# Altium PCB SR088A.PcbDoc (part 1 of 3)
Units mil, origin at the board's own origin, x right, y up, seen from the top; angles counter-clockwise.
Board outline 5010 x 3800 mil, 6 copper layers (Top Layer, Signal Layer 1, Signal Layer 2, Signal Layer 3, Signal Layer 4, Bottom Layer), stack 61.4 mil thick; 199 components, 82 nets, 478 pads, 1347 vias.
Unrouted connection lines stored in the file: 13.
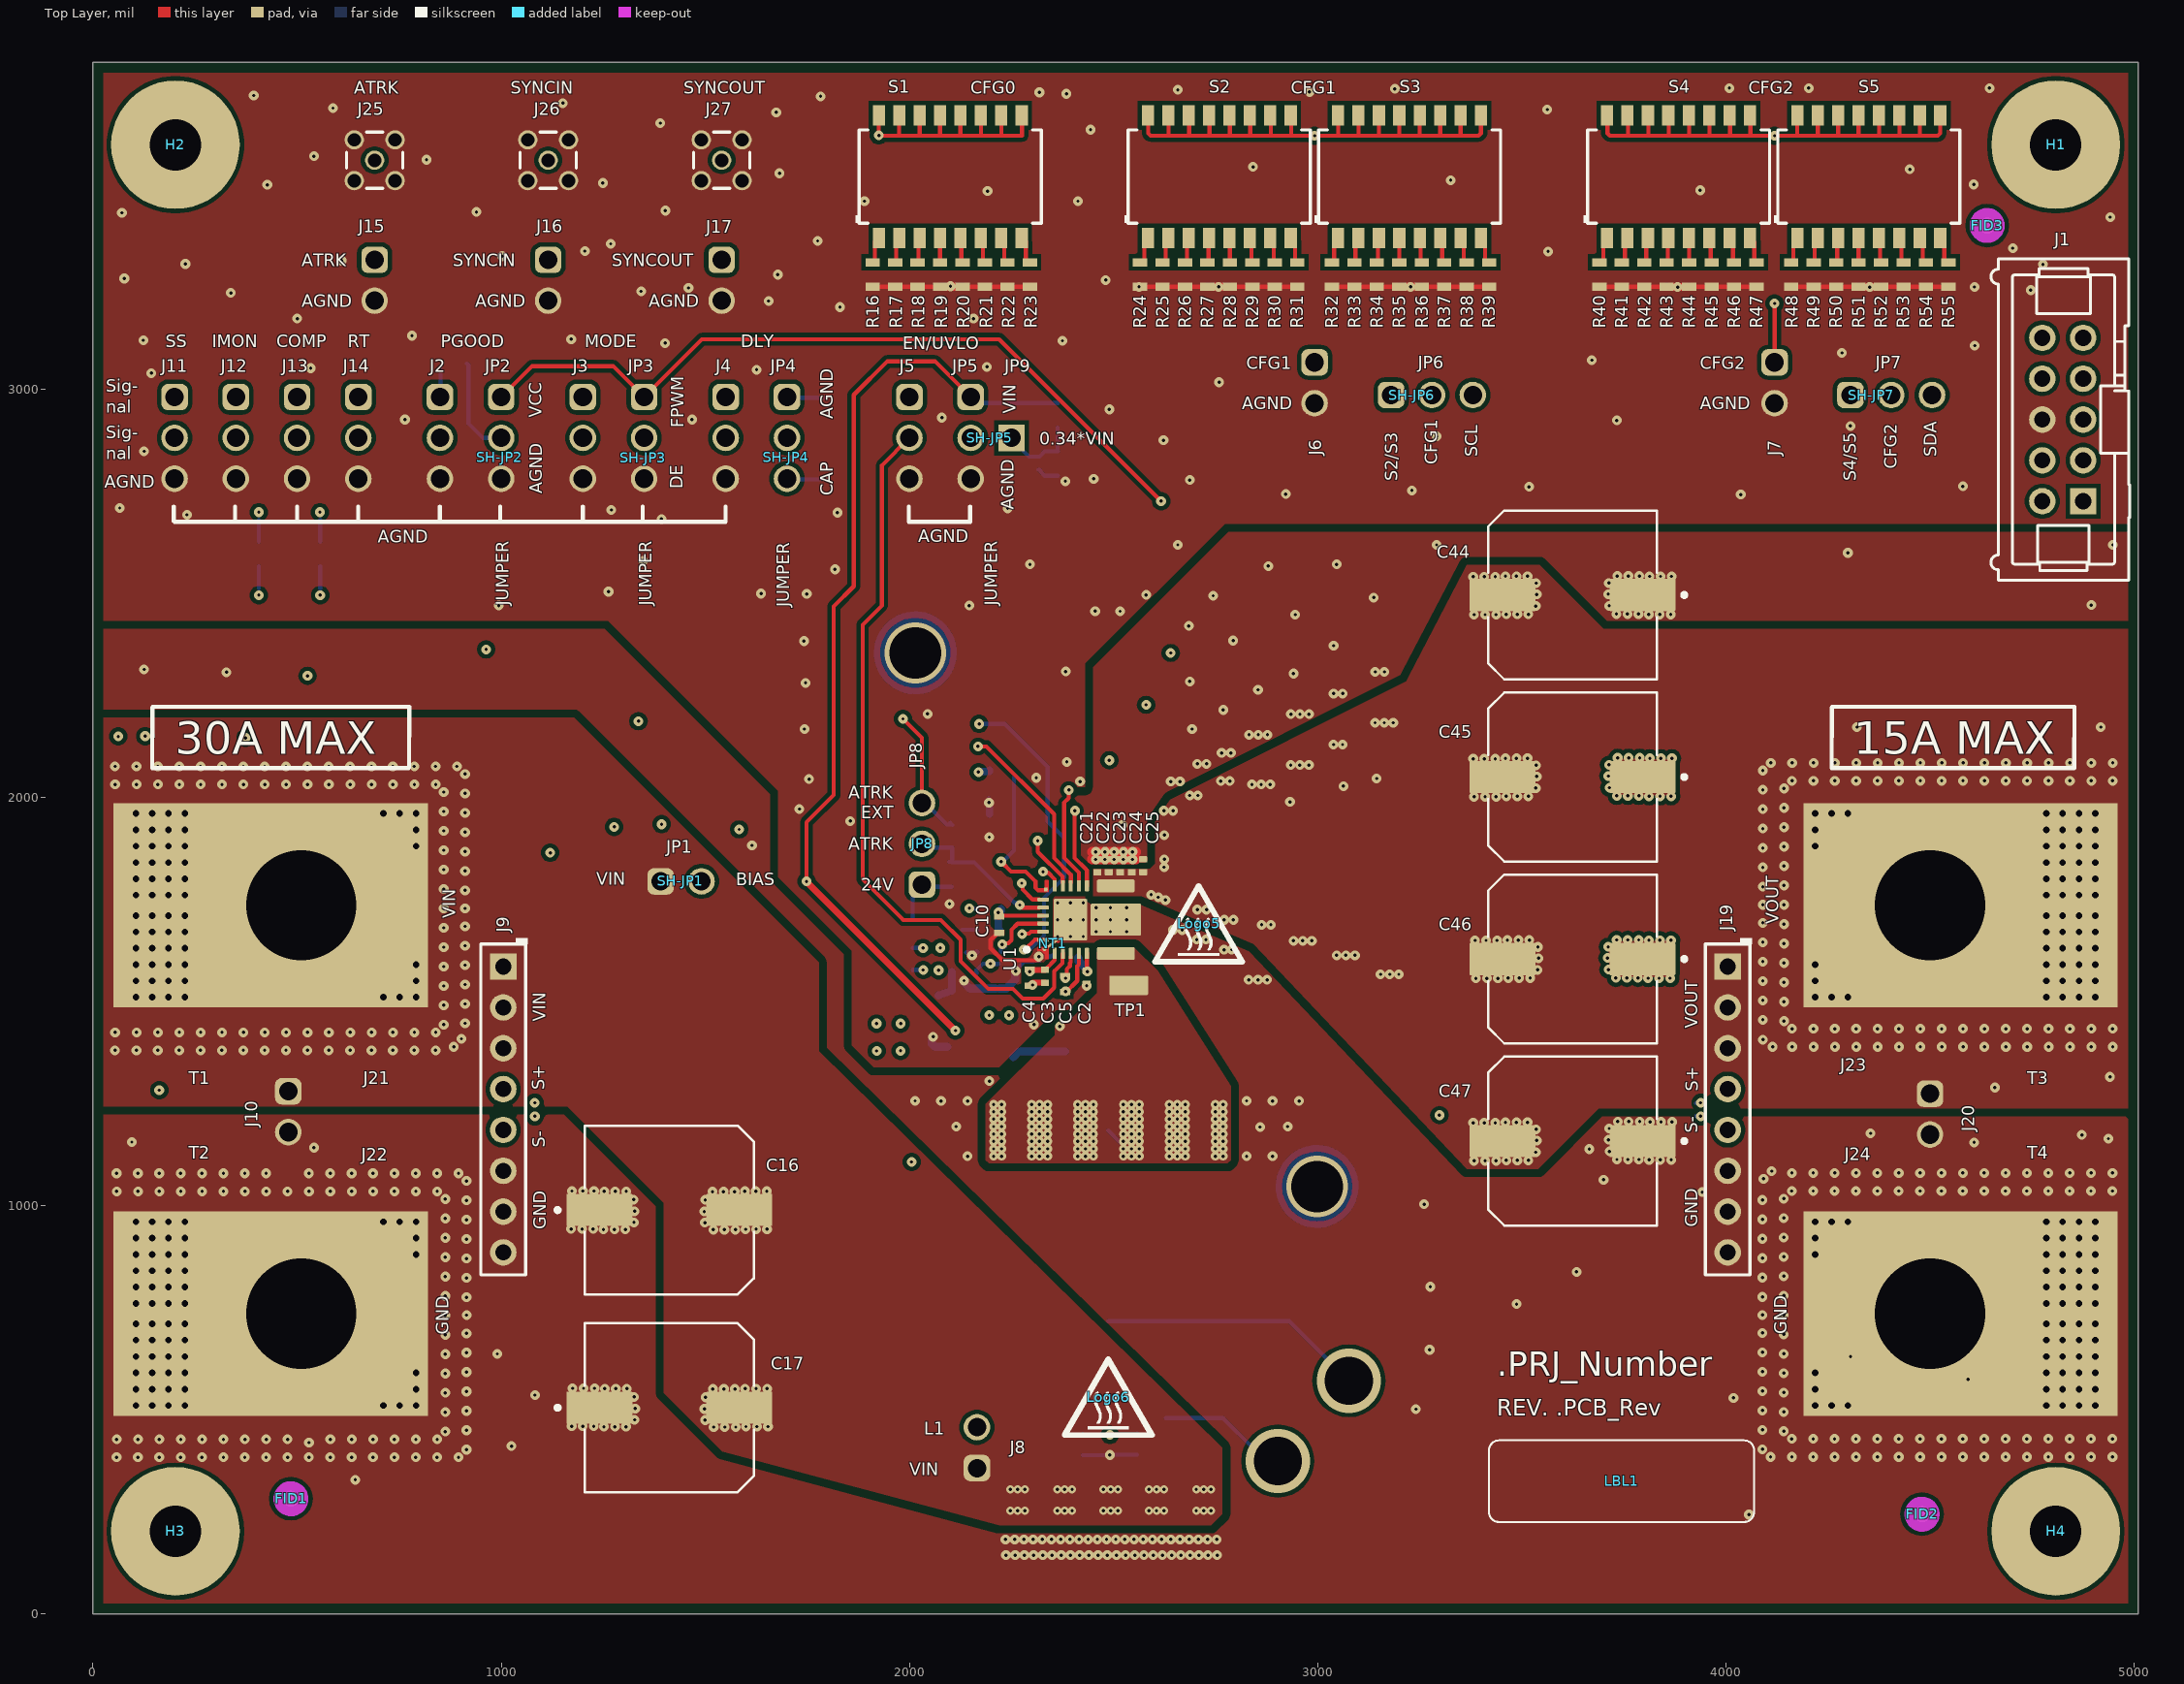
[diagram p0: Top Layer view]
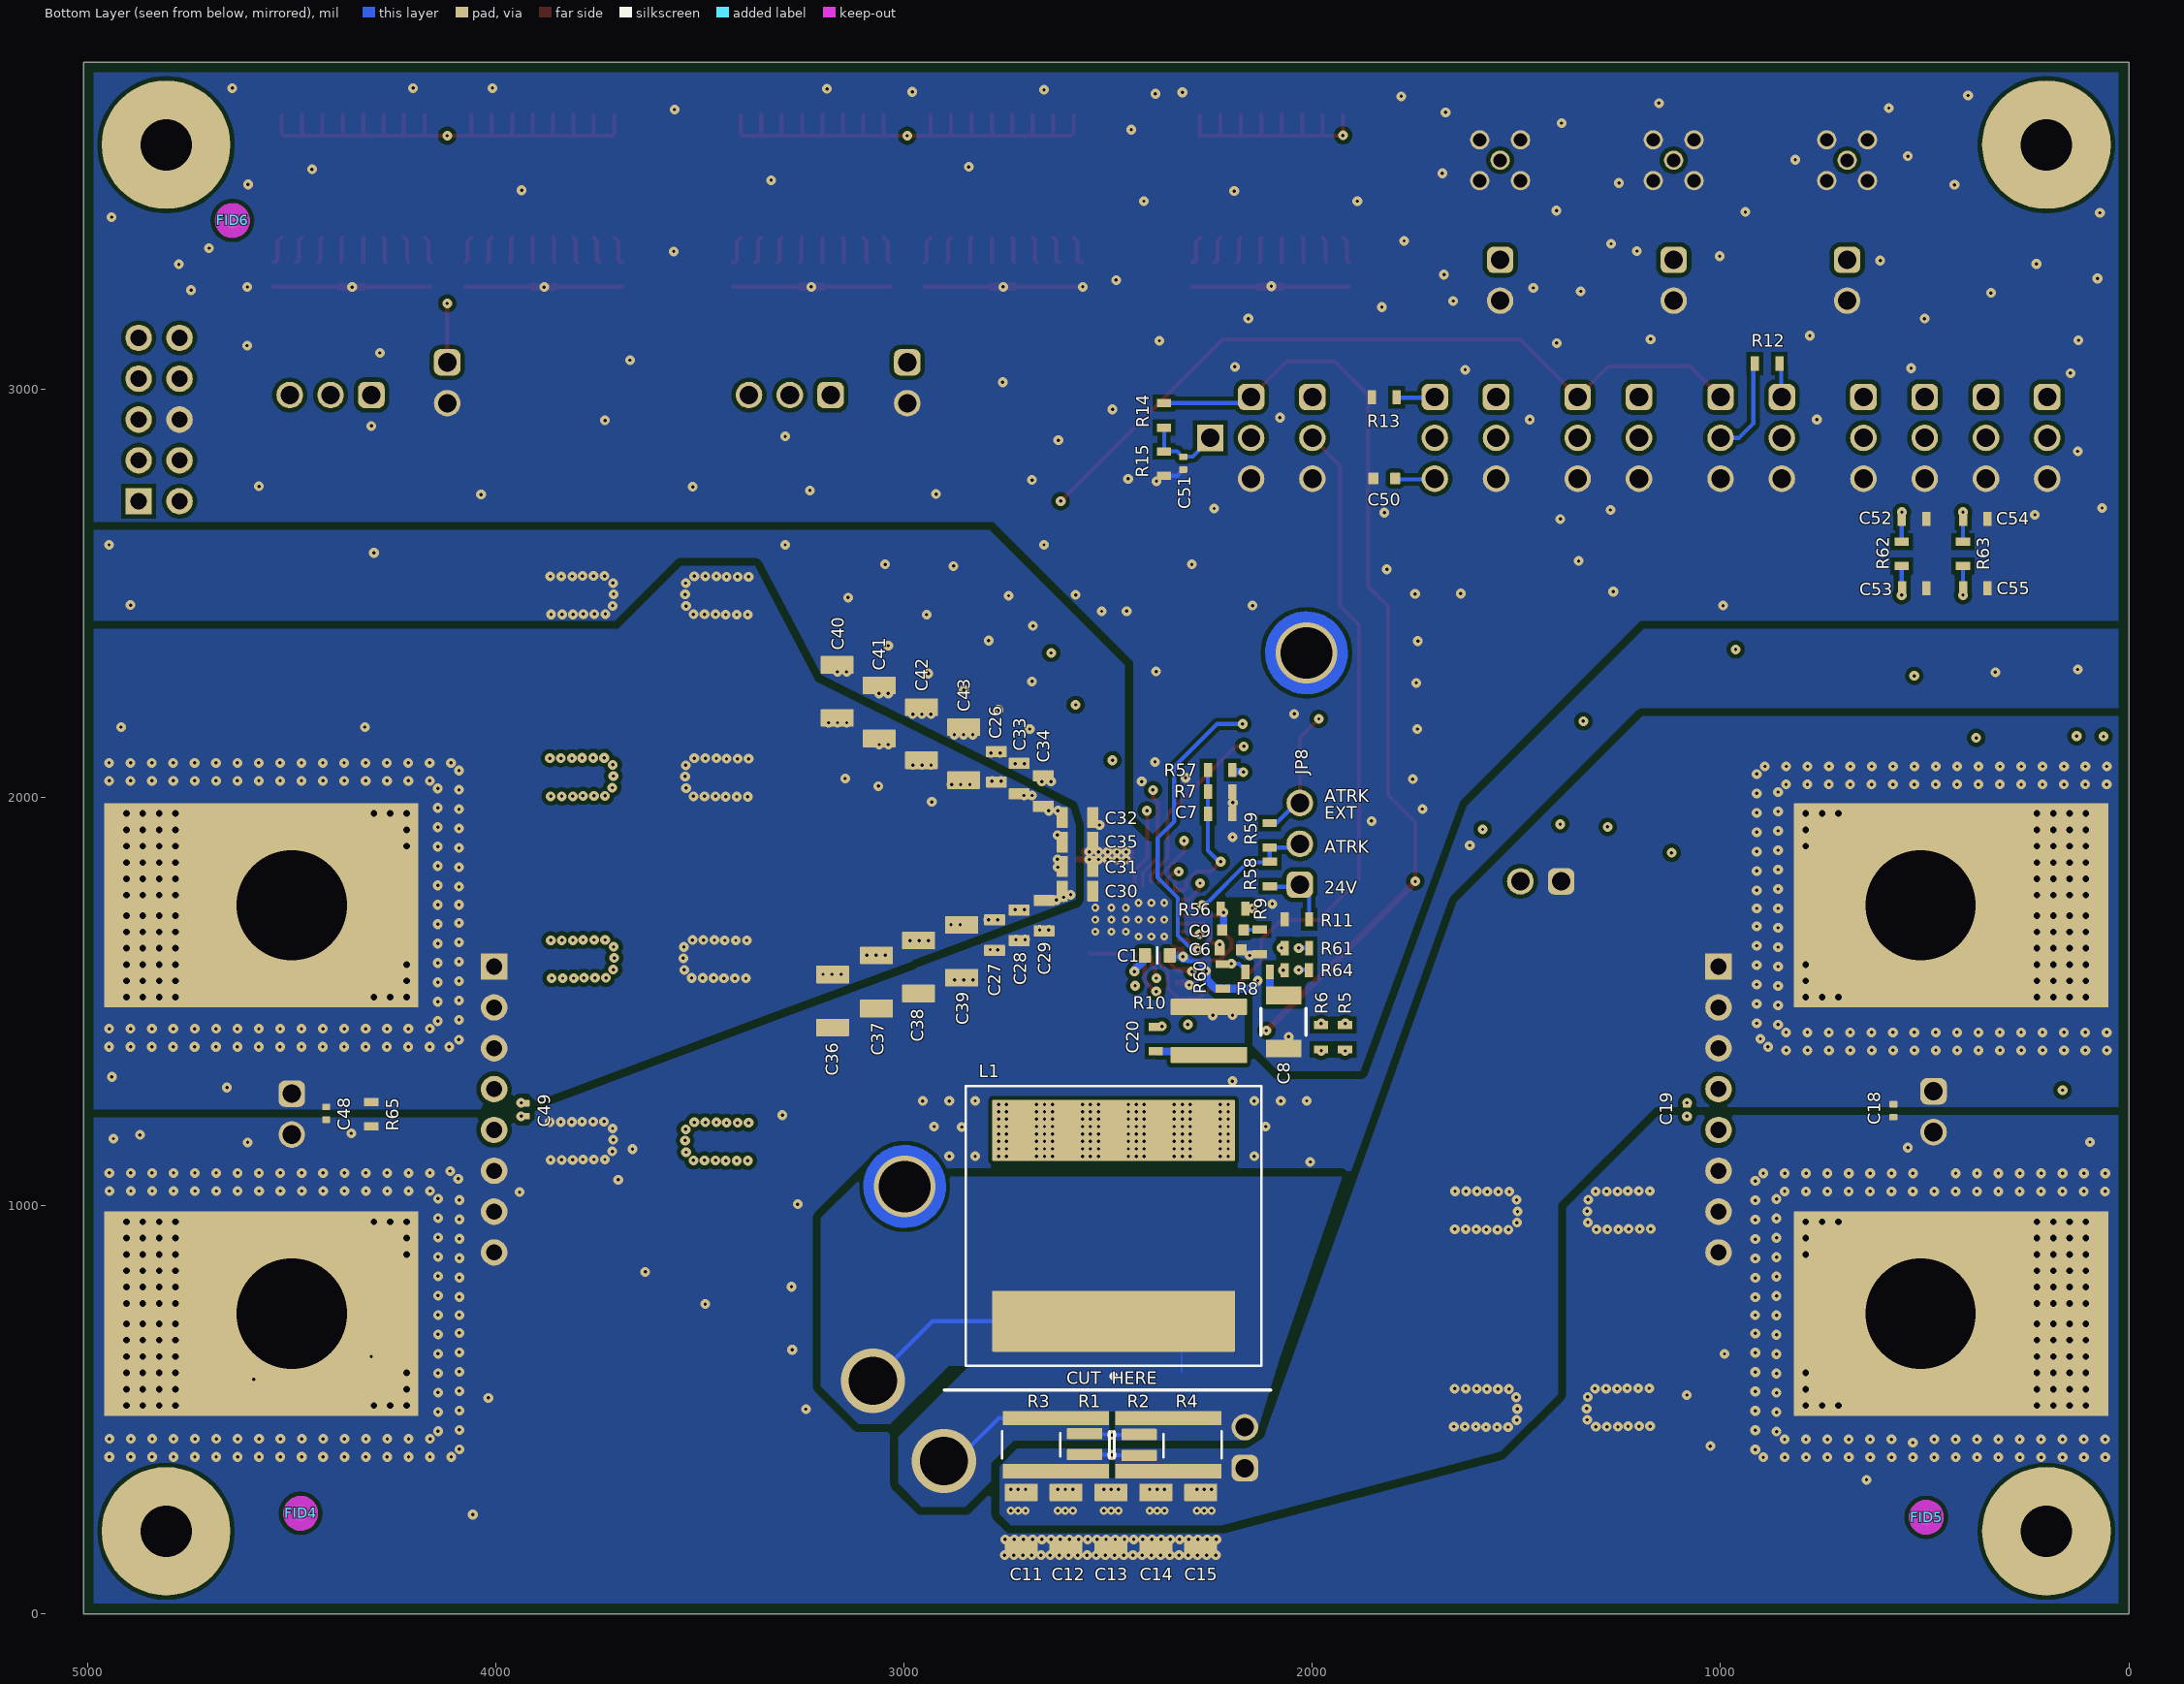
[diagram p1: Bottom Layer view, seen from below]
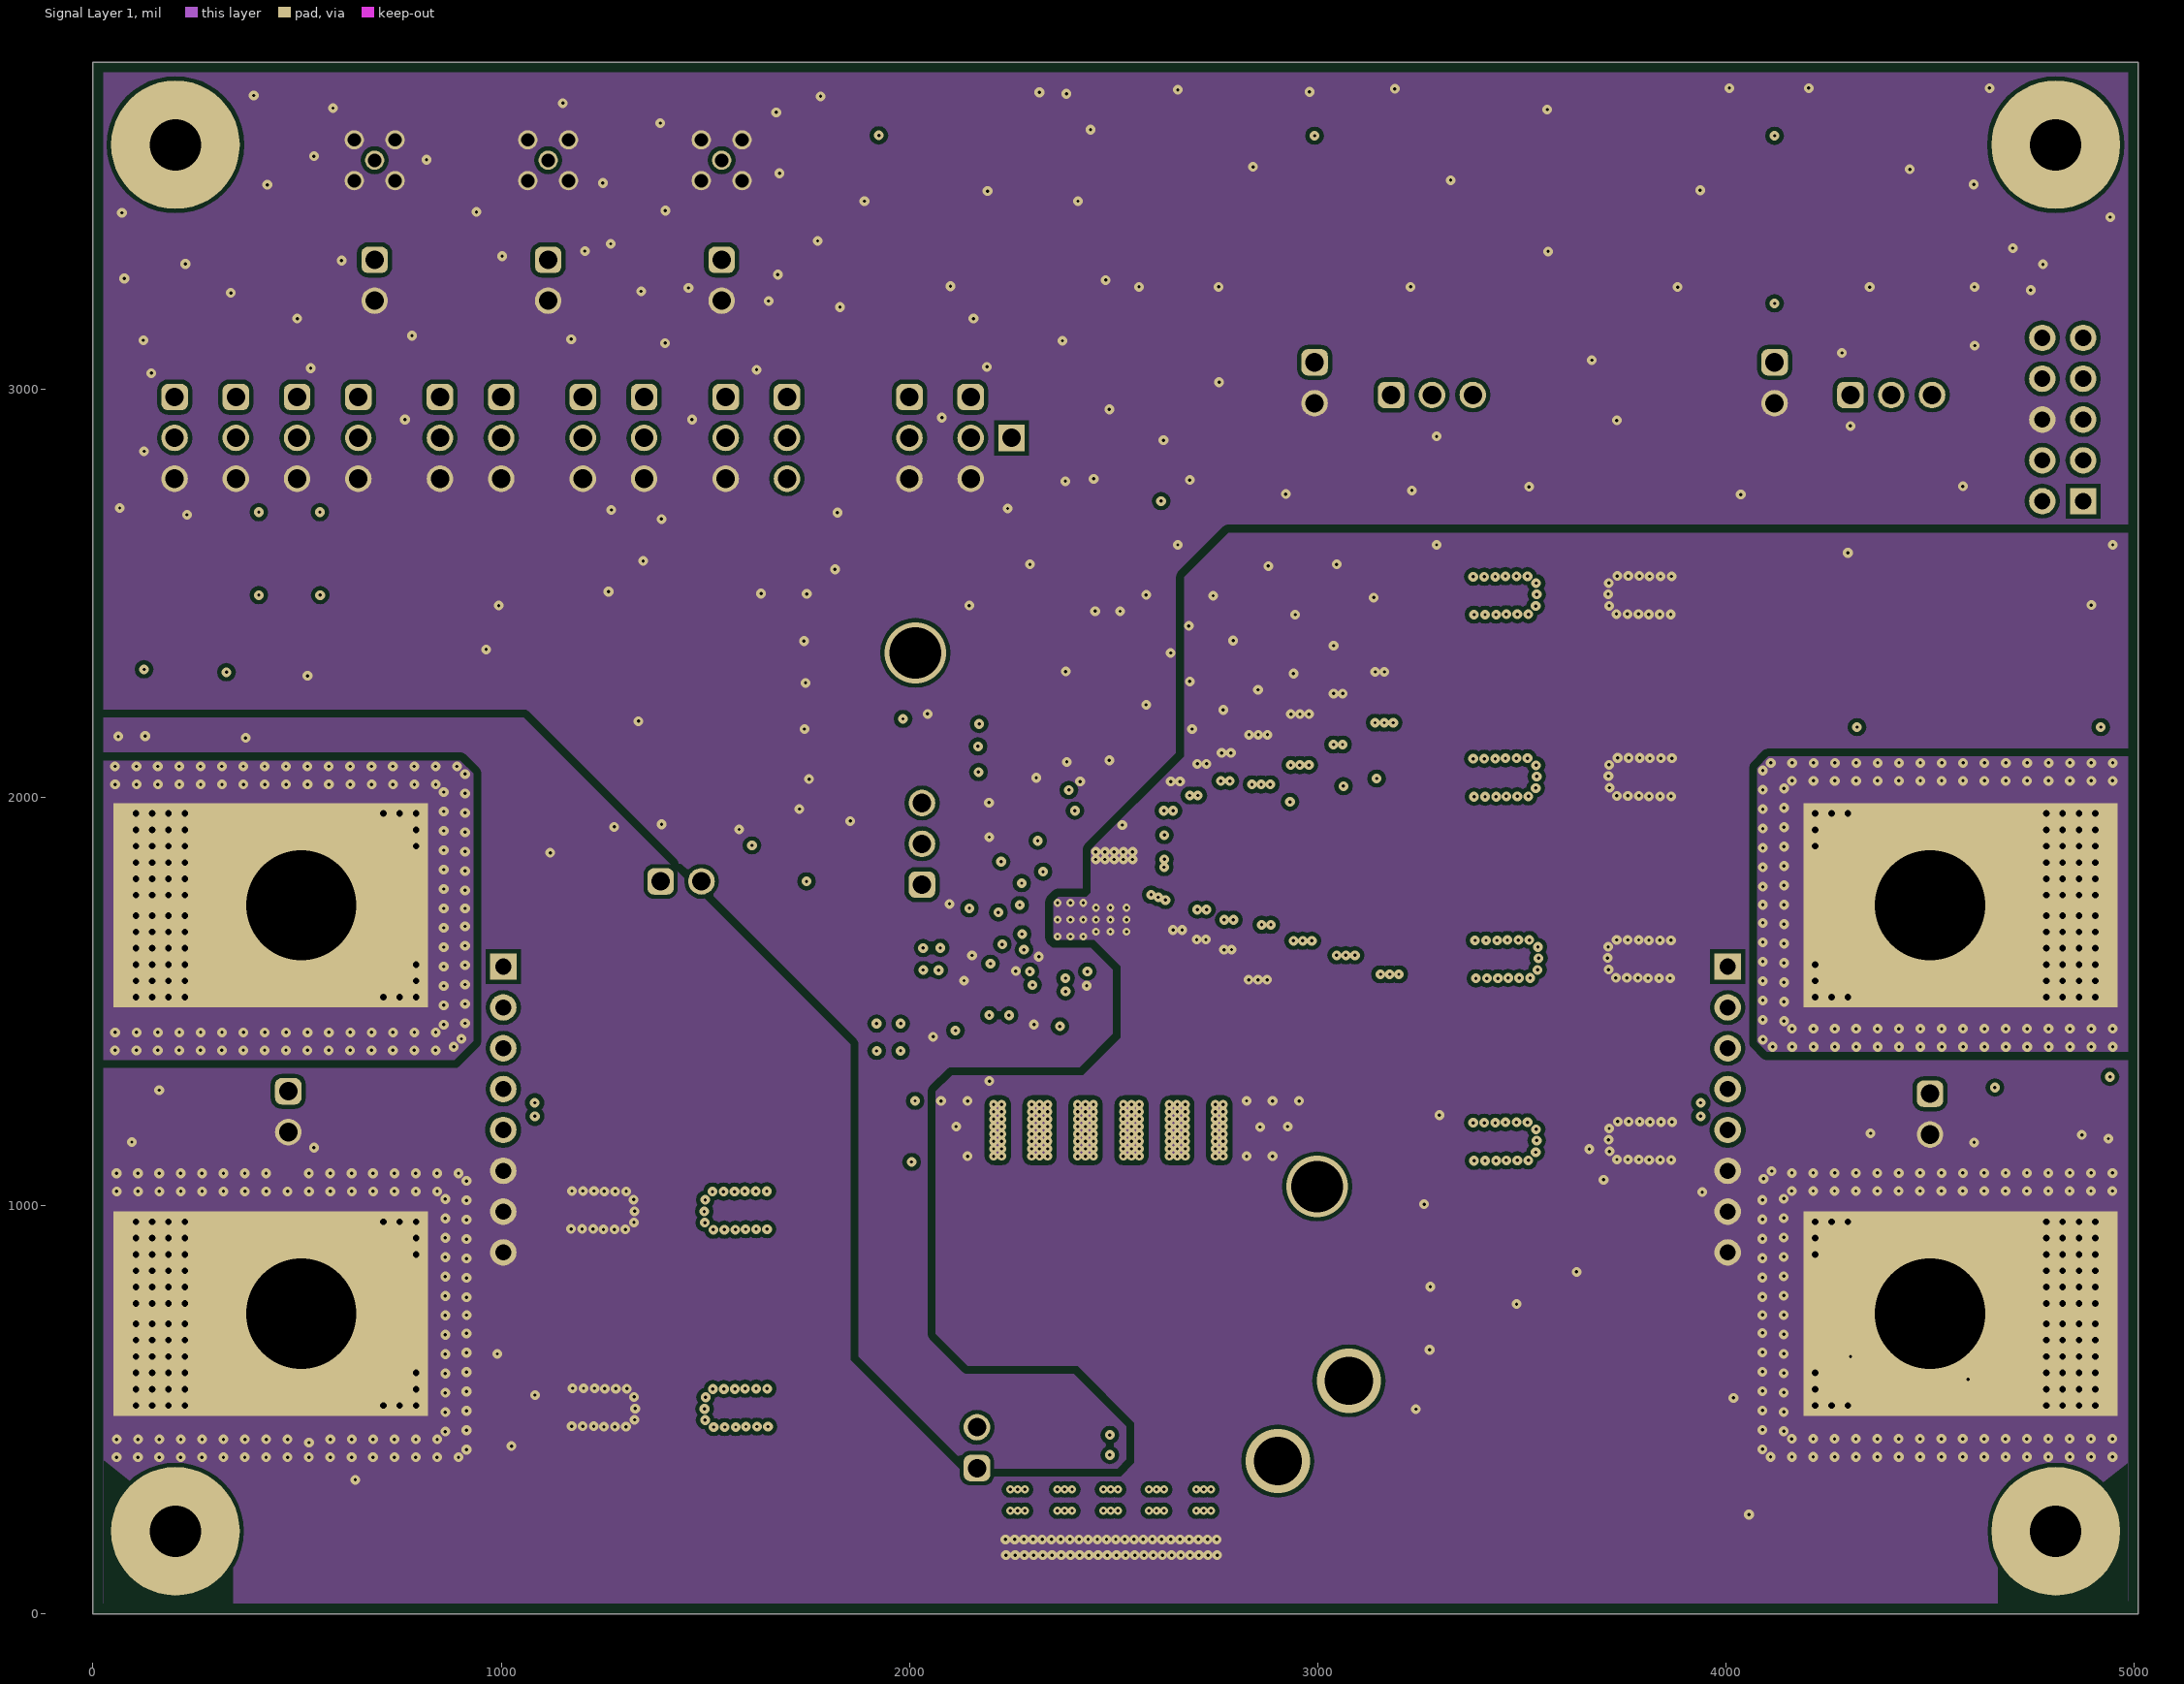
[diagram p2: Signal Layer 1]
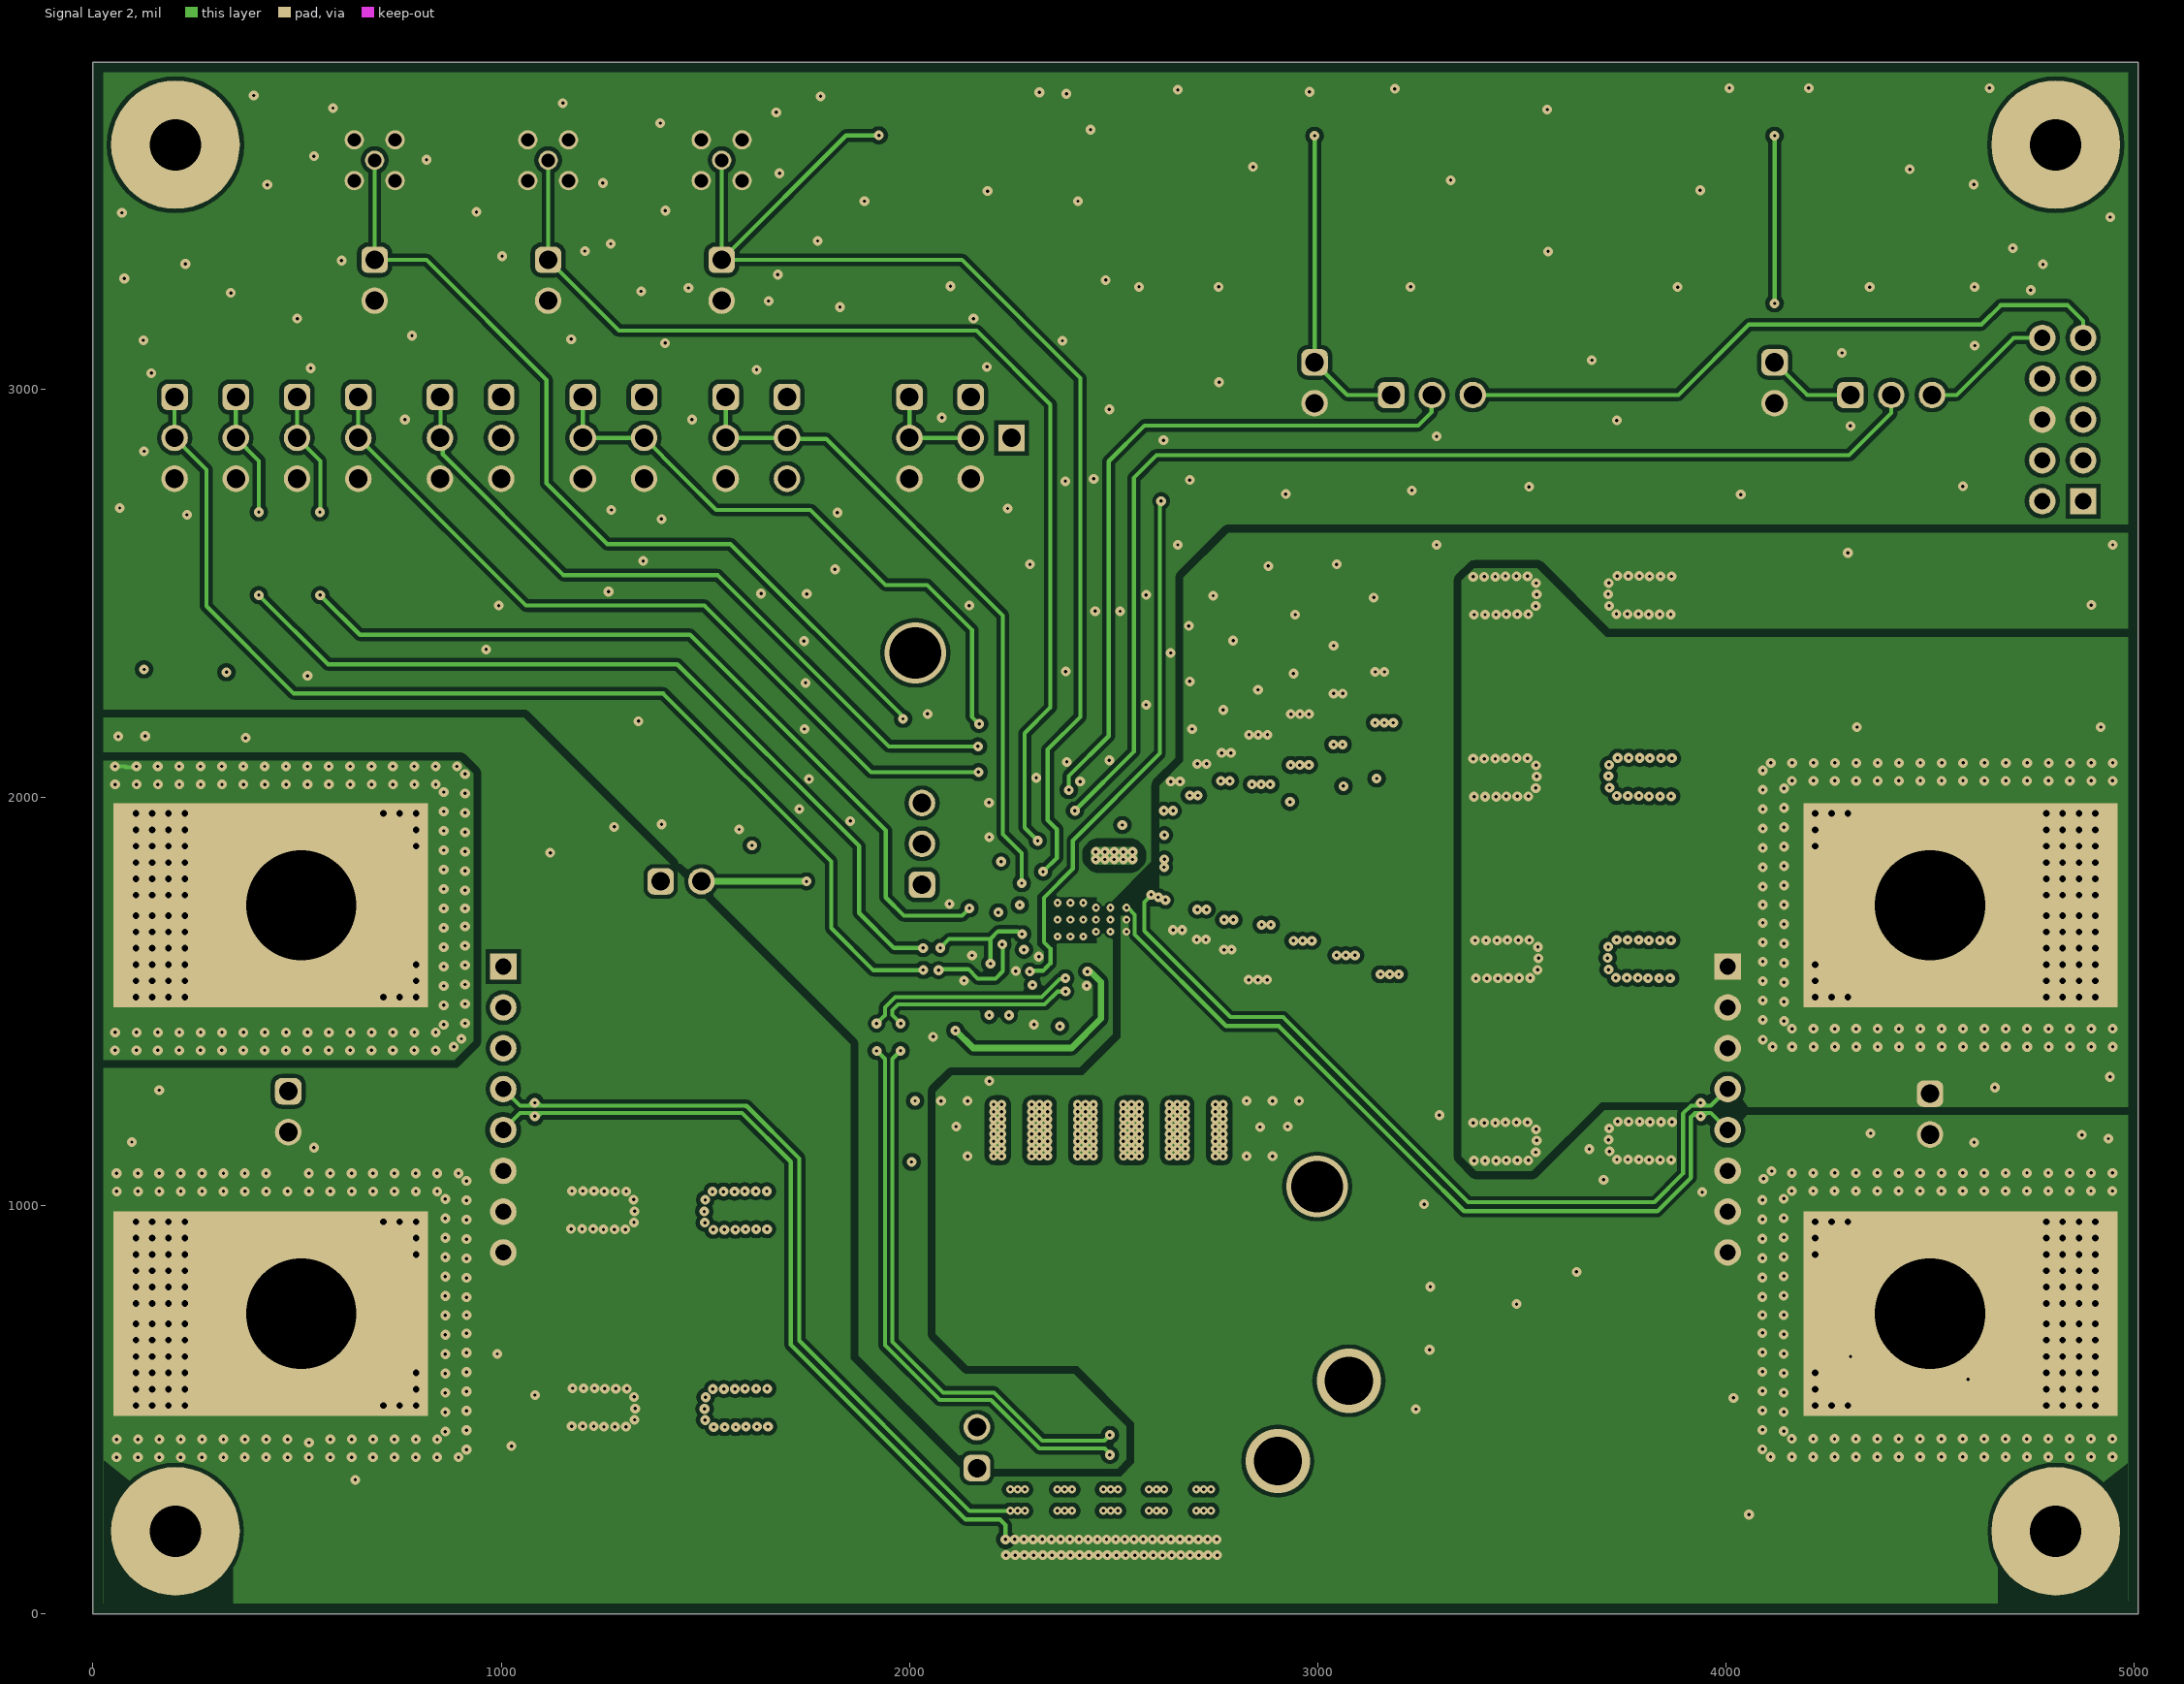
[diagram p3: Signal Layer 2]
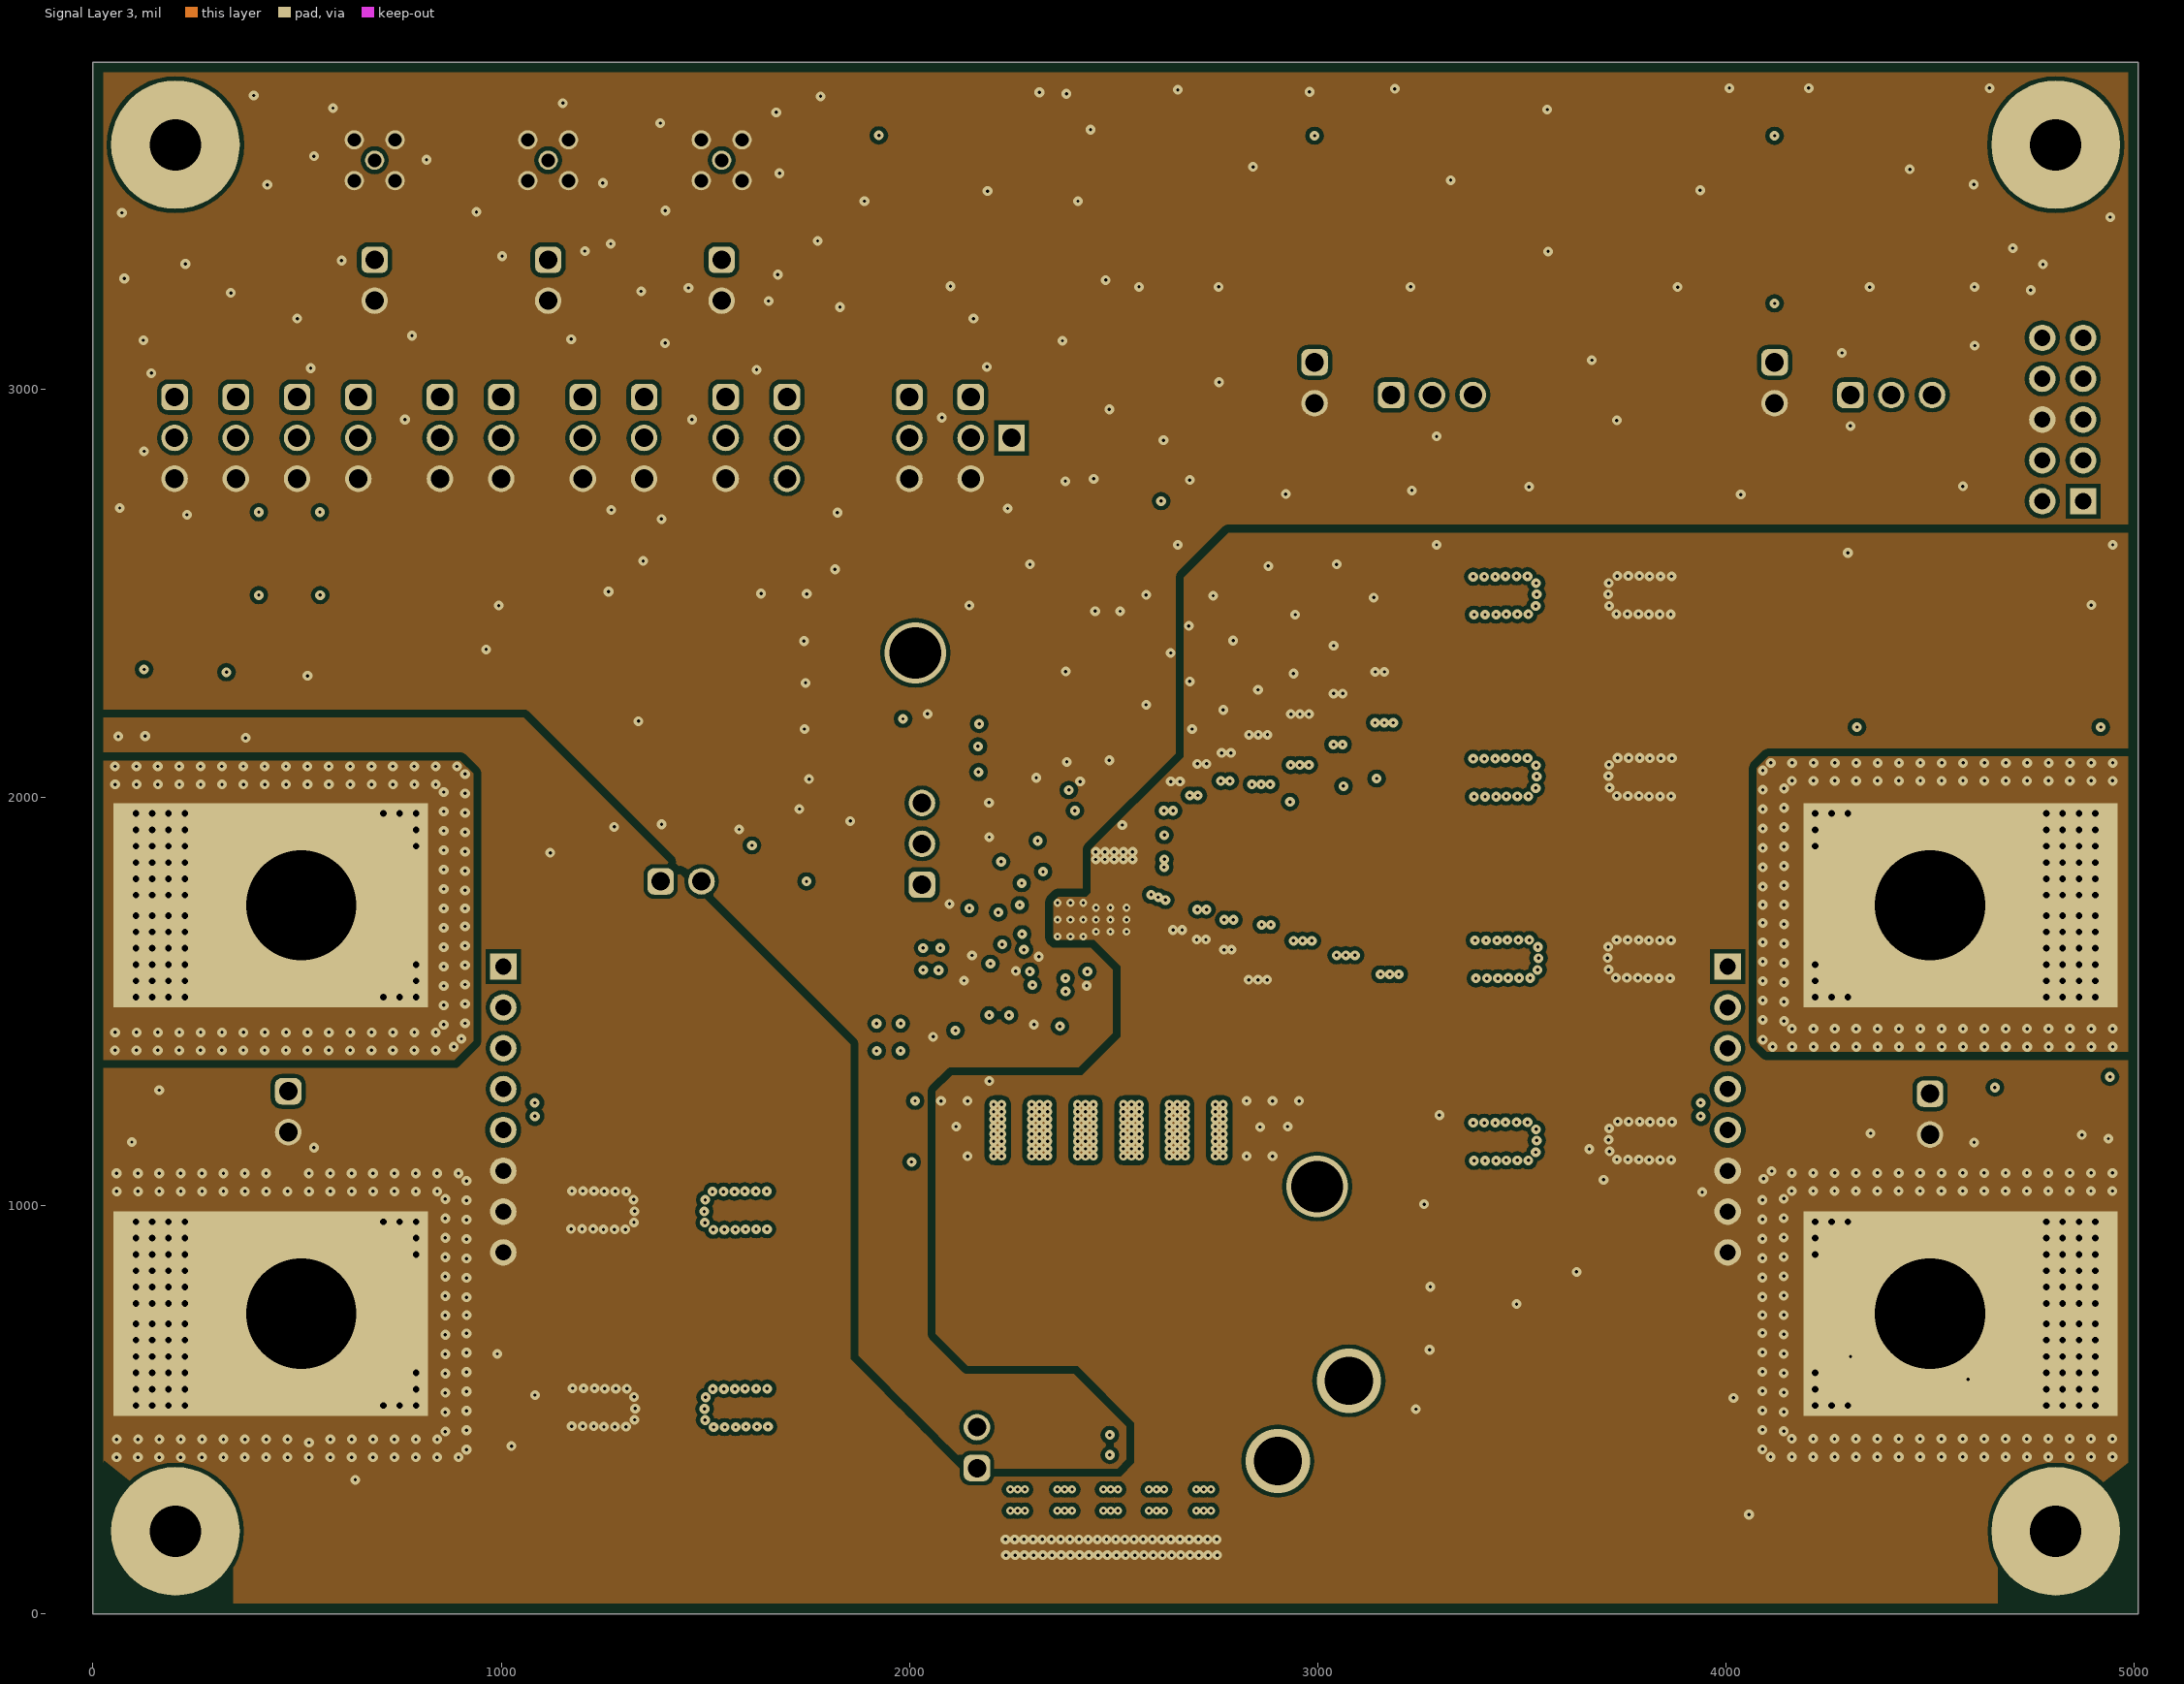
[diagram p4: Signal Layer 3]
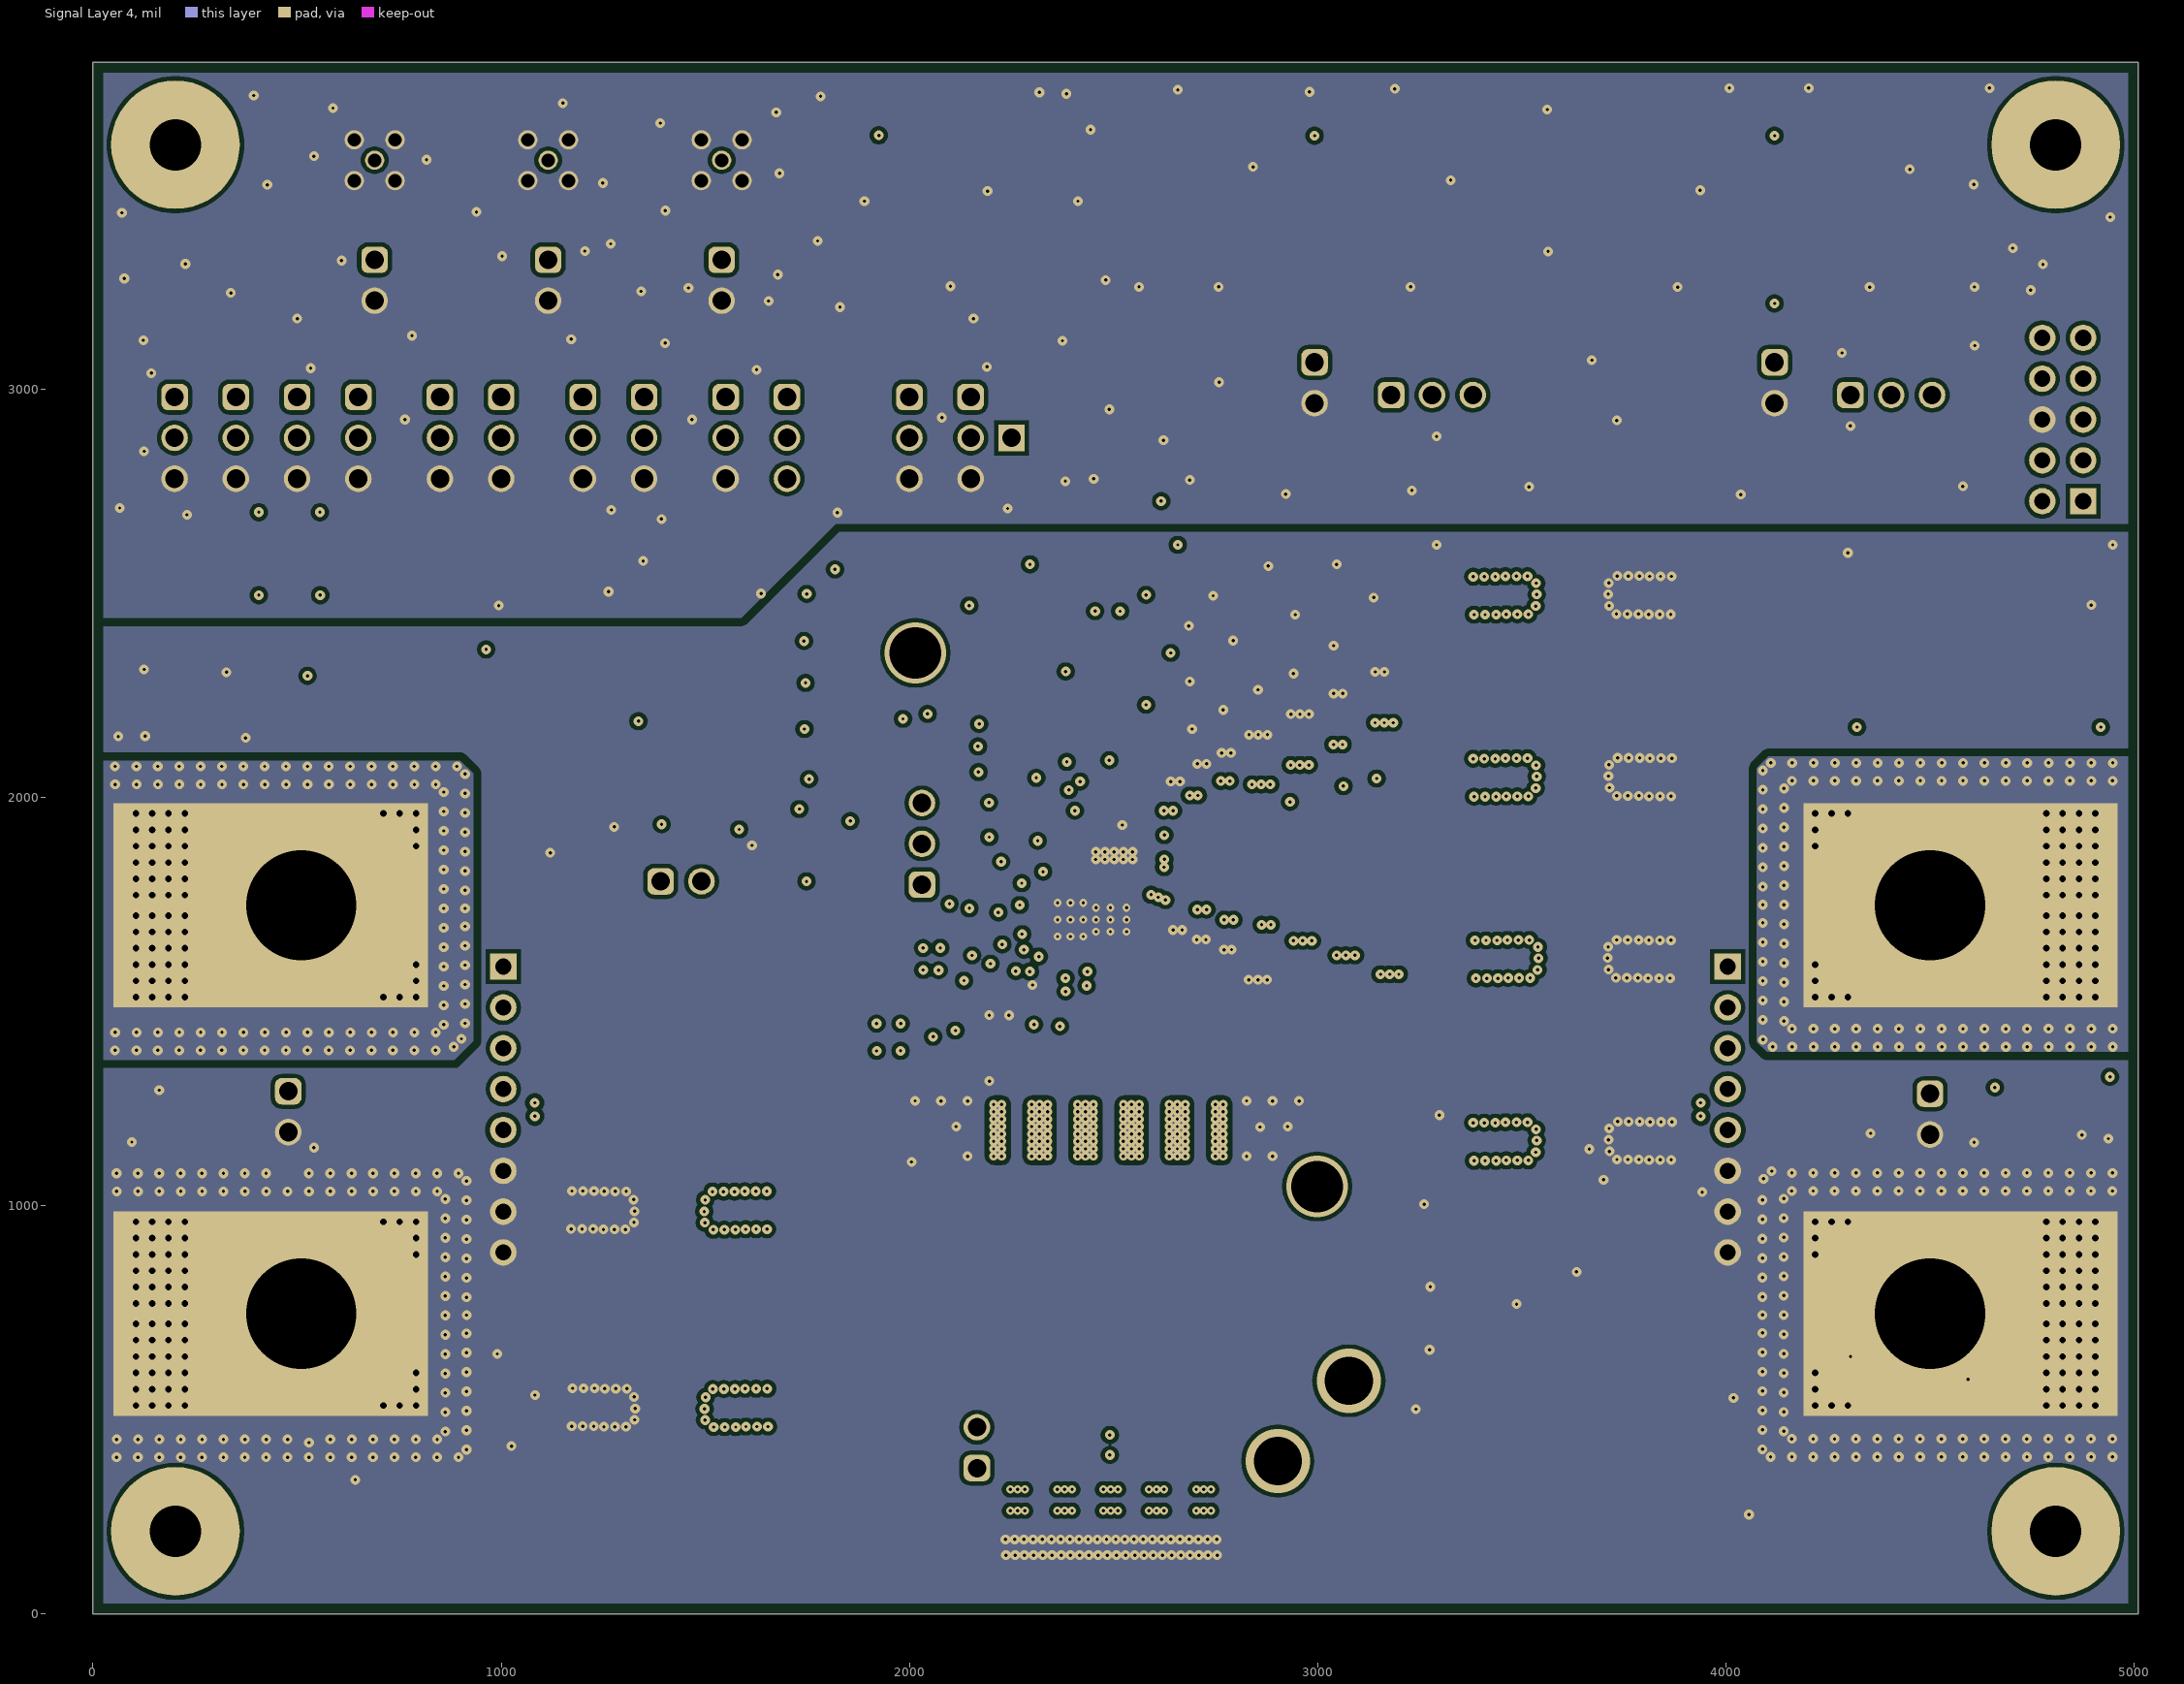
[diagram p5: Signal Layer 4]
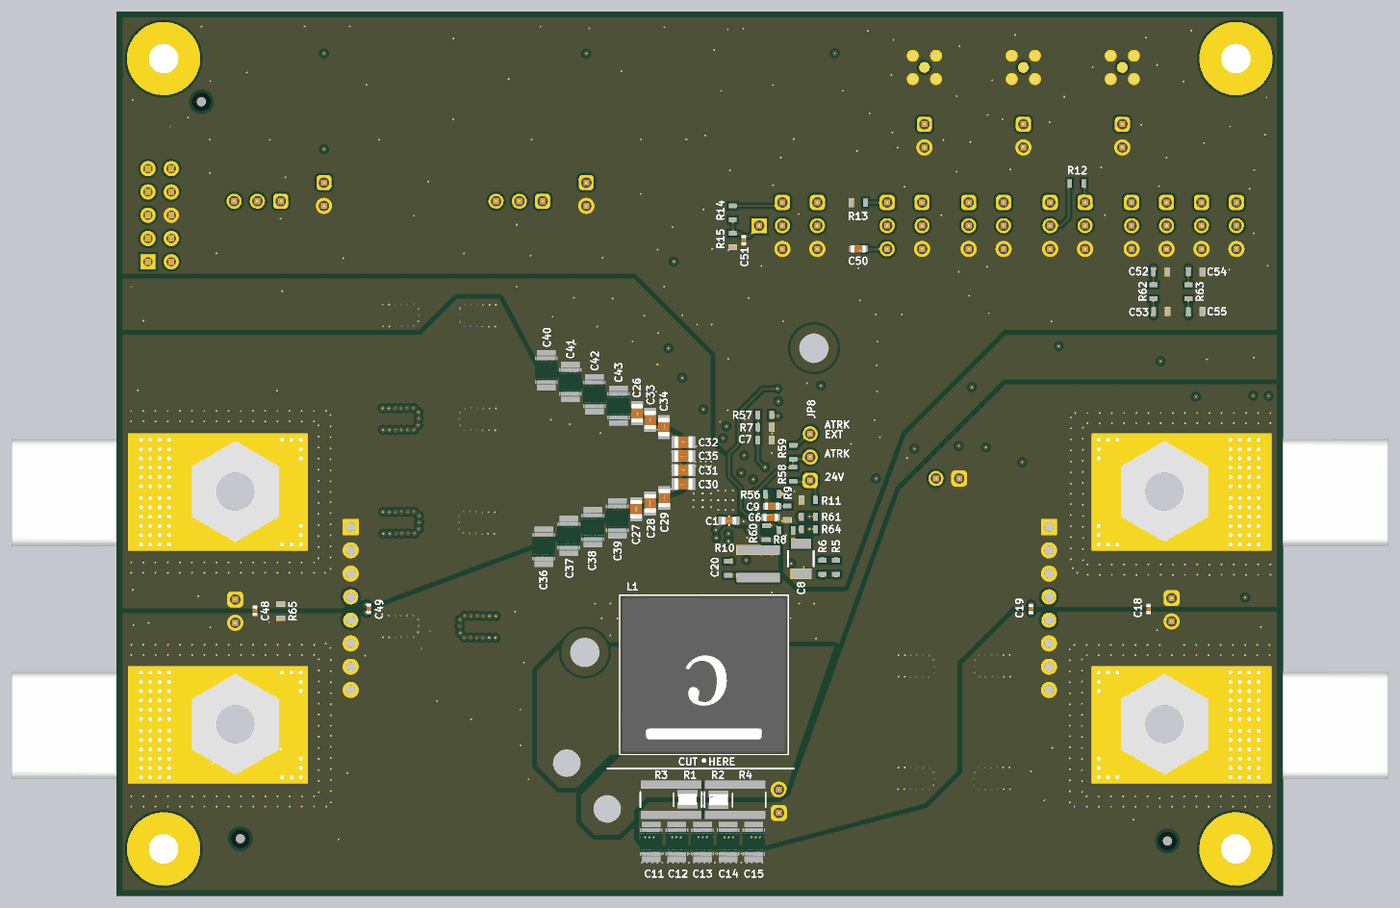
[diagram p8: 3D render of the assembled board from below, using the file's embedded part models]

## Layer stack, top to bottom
Top Solder: solder mask 0.5, Solder Resist, Dk 3.5
Top Layer: signal copper 2.8
Dielectric 1: prepreg 7, FR-4 High Tg, Dk 4.2
Signal Layer 1: signal copper 1.4
Dielectric 2: core 14, FR-4 High Tg, Dk 4.2
Signal Layer 2: signal copper 1.4
Dielectric 4: prepreg 8.2, FR-4 High Tg, Dk 4.2
Signal Layer 3: signal copper 1.4
Dielectric 5: core 14, FR-4 High Tg, Dk 4.2
Signal Layer 4: signal copper 1.4
Dielectric 3: prepreg 7, FR-4 High Tg, Dk 4.2
Bottom Layer: signal copper 2.8
Bottom Solder: solder mask 0.5, Solder Resist, Dk 3.5

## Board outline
0,0 0,3800 5010,3800 5010,0

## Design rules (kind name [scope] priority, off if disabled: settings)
AcuteAngle [All] p1: minimum=4.50000000000000E+0001 checktracksonly=FALSE
AssemblyTestPointUsage [All] p1: valid=2
BoardOutlineClearance BoardOutlineClearance_MountingHoles [OnCopper and InComponentClass('Mounting Holes')] p1: gap=39.37 ignorepadtopadclearanceinfootprint=FALSE
BoardOutlineClearance BoardOutlineClearance_Poly [OnCopper and IsPoly] p2: gap=25 ignorepadtopadclearanceinfootprint=FALSE
BoardOutlineClearance [OnCopper and Not InComponentClass('Logo') and not InComponentClass('FiducialMark') and not InRegion(1000,500,4000,800) and not InPoly] p3: gap=40 ignorepadtopadclearanceinfootprint=FALSE
Clearance Clearance_IC [WithinRoom('Controller')] p1: gap=5.5 ignorepadtopadclearanceinfootprint=TRUE
Clearance Clearance_Keepouts [((IsTrack Or IsArc) And Not InPoly) And IsFree and IsKeepOut vs ((IsTrack Or IsArc) And Not InPoly) And IsFree and IsKeepOut] p2: gap=0 ignorepadtopadclearanceinfootprint=FALSE
Clearance Clearance_Poly [InPolygon] p3: gap=10 ignorepadtopadclearanceinfootprint=TRUE except(20: Poly-Poly)
Clearance Clearance_FiducialMark [IsKeepOut and InComponentClass('FiducialMark') vs IsPad and InComponentClass('FiducialMark')] p4: gap=0 ignorepadtopadclearanceinfootprint=FALSE
Clearance [All] p5: gap=7.87 ignorepadtopadclearanceinfootprint=TRUE
ComponentClearance ComponentClearance_Caps [InComponent('C11') or InComponent('C12') or InComponent('C13') or  InComponent('C14') or InComponent('C15') or InComponent('C21') or InComponent('C22') or InComponent('C23') or InComponent('C24') or InComponent('C25') or InComponent('C26') or InComponent('C27') or   InComponent('C28') or InComponent('C29') or InComponent('C30') or InComponent('C31') or InComponent('C32') or InComponent('C33') or  InComponent('C34') or InComponent('C35') or InComponent('C36') or InComponent('C37') or InComponent('C38') or InComponent('C39') or   InComponent('C40') or InComponent('C41') or InComponent('C42') or InComponent('C43')] p1: gap=4 collisioncheckmode=3 verticalgap=10 showdistances=FALSE
ComponentClearance ComponentClearance_Banana [HasFootprint('Johnson_108-0740-001') vs HasFootprint('Panduit_CXS70-14-C')] p2: gap=0 collisioncheckmode=3 verticalgap=0 showdistances=FALSE
ComponentClearance ComponentClearance_JP_Res [InComponent('JP4') or InComponent('JP5') or  InComponent('JP8') or InComponent('JP9') or  InComponent('R1') or InComponent('R2') or InComponent('R3') or InComponent('R4') or InComponent('TP1')] p3: gap=0 collisioncheckmode=3 verticalgap=0 showdistances=FALSE
ComponentClearance ComponentClearance_NT [InComponent('U1') or InComponent('NT1')] p4: gap=-1 collisioncheckmode=3 verticalgap=-1 showdistances=FALSE
ComponentClearance ComponentClearance_MountingHoles_FiducialMarks [InComponentClass('Mounting Holes') vs InComponentClass('FiducialMark')] p5: gap=50 collisioncheckmode=3 verticalgap=10 showdistances=FALSE
ComponentClearance ComponentClearance_Shunt [InComponentClass('Header') vs InComponentClass('Shunt') or InComponent('SH-JP1') or InComponent('SH-JP2') or InComponent('SH-JP3') or InComponent('SH-JP4') or InComponent('SH-JP5') or InComponent('SH-JP6') or  InComponent('SH-JP8')  or  InComponent('SH-JP9')] p6: gap=0 collisioncheckmode=3 verticalgap=0 showdistances=FALSE
ComponentClearance ComponentClearance_Logo [InComponentClass('Logo')] p7: gap=30 collisioncheckmode=3 verticalgap=10 showdistances=FALSE
ComponentClearance ComponentClearance_ScrewToNut [(HasFootprint('NY PMS 440 0025 PH')) vs (HasFootprint('Keystone_1902C'))] p8: gap=5 collisioncheckmode=3 verticalgap=10 showdistances=FALSE
ComponentClearance ComponentClearance_MountingHoles [InComponentClass('Mounting Holes')] p9: gap=100 collisioncheckmode=3 verticalgap=100000 showdistances=FALSE
ComponentClearance ComponentClearance_SmallPassives [HasFootprint('0201*') or HasFootprint('0402*') or HasFootprint('0508') or HasFootprint('0603*') or HasFootprint('0612') or HasFootprint('0805*') or HasFootprint('0815*') or HasFootprint('0830*') or HasFootprint('1206*') or HasFootprint('1210*') or HasFootprint('1808*') or HasFootprint('1812*') or HasFootprint('1825*') or HasFootprint('2010*') or HasFootprint('2220*') or HasFootprint('2225*') or HasFootprint('2512*') or HasFootprint('2728*') or HasFootprint('3518*') vs HasFootprint('0201*') or HasFootprint('0402*') or HasFootprint('0508') or HasFootprint('0603*') or HasFootprint('0612') or HasFootprint('0805*') or HasFootprint('0815*') or HasFootprint('0830*') or HasFootprint('1206*') or HasFootprint('1210*') or HasFootprint('1808*') or HasFootprint('1812*') or HasFootprint('1825*') or HasFootprint('2010*') or HasFootprint('2220*') or HasFootprint('2225*') or HasFootprint('2512*') or HasFootprint('2728*') or HasFootprint('3518*')] p10: gap=14.96 collisioncheckmode=3 verticalgap=10 showdistances=FALSE
ComponentClearance ComponentClearance_THtoSMT [IsThruComponent vs IsSMTComponent] p11: gap=30 collisioncheckmode=3 verticalgap=30 showdistances=FALSE
ComponentClearance ComponentClearance_THtoTH [IsThruComponent vs IsThruComponent] p12: gap=20 collisioncheckmode=3 verticalgap=30 showdistances=FALSE
ComponentClearance [All] p13: gap=15 collisioncheckmode=3 verticalgap=10 showdistances=FALSE
DiffPairsRouting [All] p1: maxlimit=100 minlimit=10 mostfreqgap=10 toplayer_minwidth=15 toplayer_maxwidth=15 toplayer_prefwidth=15 midlayer1_minwidth=15 midlayer1_maxwidth=15 midlayer1_prefwidth=15 midlayer2_minwidth=15 midlayer2_maxwidth=15 midlayer2_prefwidth=15 midlayer3_minwidth=15 midlayer3_maxwidth=15 midlayer3_prefwidth=15 midlayer4_minwidth=15 midlayer4_maxwidth=15 midlayer4_prefwidth=15 bottomlayer_minwidth=15 bottomlayer_maxwidth=15 bottomlayer_prefwidth=15 maxuncoupledlength=1000
FabricationTestPointUsage TestPointUsage [All] p1: valid=2 allowmultiple=FALSE
FabricationTestpoint Testpoint [All] p1: side=3 testpointundercomponent=TRUE minsize=40 maxsize=100 preferedsize=60 minholesize=0 maxholesize=40 preferedholesize=32 testpointgrid=1 allowsidetop=TRUE allowsidebottom=TRUE usegrid=TRUE gridtolerance=0.01
FanoutControl Fanout_LCC [IsLCC] p1: bgadir=Out bgaviamode=Centered fanoutstyle=Auto fanoutdirection=Alternating viagrid=1 // Fanout_LCC (Default Rule)
FanoutControl Fanout_BGA [IsBGA] p2: bgadir=Out bgaviamode=Centered fanoutstyle=Auto fanoutdirection=Alternating viagrid=1 // Fanout_BGA (Default Rule)
FanoutControl Fanout_Default [All] p4: bgadir=Out bgaviamode=Centered fanoutstyle=Auto fanoutdirection=Alternating viagrid=1 // Fanout_Default (Default Rule)
FanoutControl Fanout_Small [(CompPinCount < 5)] p5: bgadir=Out bgaviamode=Centered fanoutstyle=Auto fanoutdirection=OutThenIn viagrid=1 // Fanout_Small (Default Rule)
HoleSize [All] p1: absolutevalues=TRUE maxlimit=270 minlimit=7.87 maxpercent=80.000 minpercent=20.000
HoleToHoleClearance HoleToHoleClearance_Banana [HasFootprint('Johnson_108-0740-001') vs HasFootprint('Panduit_CXS70-14-C')] p1: gap=0 allowstackedmicrovias=TRUE
HoleToHoleClearance [All] p2: gap=10 allowstackedmicrovias=TRUE
MinimumAnnularRing MinimumAnnularRing_ThermalPadVias [IsVia and InAnyComponent] p1: minimumring=3.5
MinimumAnnularRing [All] p2: minimumring=6
MinimumSolderMaskSliver MinimumSolderMaskSliver_Logo [InComponentClass('Logo') vs InComponentClass('Logo')] p1: minsoldermaskwidth=0.7
MinimumSolderMaskSliver [All] p2: minsoldermaskwidth=3.94
PlaneConnect [All] p1: planeconnectstyle=Direct reliefexpansion=10 reliefentries=4 reliefconductorwidth=10 reliefairgap=10
PolygonConnect PolygonConnect_solder [InComponent('C50') or InComponent('C51') or InComponent('R13') or InComponent('R7') or InComponent('C7') or InComponent('C6') or InComponent('R9') or InComponent('R11') or InComponent('R15')] p1: connectstyle=Direct reliefconductorwidth=10 reliefentries=4 polygonreliefangle="90 Angle" airgapwidth=10
PolygonConnect [All] p2: connectstyle=Direct reliefconductorwidth=10 reliefentries=4 polygonreliefangle="90 Angle" airgapwidth=10
RoomDefinition Controller [False] p1: confinementstyle=ConfineIn formatcopy=TRUE lockcomponents=FALSE outline 2542.29,1752.75 2330.44,1752.75 2330.44,1623.75 2542.29,1623.75
RoutingVias ThermalPadVias [IsVia and InAnyComponent] p1: holewidth=7.87 width=19.68 viastyle="Through Hole" minholewidth=7.87 minwidth=14 maxholewidth=16 maxwidth=32
RoutingVias [All] p2: holewidth=16 width=34 viastyle="Through Hole" minholewidth=7.87 minwidth=20 maxholewidth=270 maxwidth=270
SilkToBoardRegionClearance [Not ((IsComment or IsDesignator) And (Hide <> 'False')) and not InRegion(1000,500,4000,800)] p1:
SilkToSilkClearance SilkToSilkClearance_Pb-FreeLogo [(HasFootprint('Pb-Free_Overlay_Medium') OR HasFootprint('Pb-Free_Overlay_Small')) vs (HasFootprint('Pb-Free_Overlay_Medium') OR HasFootprint('Pb-Free_Overlay_Small'))] p1: silktosilkclearance=0
SilkToSilkClearance [All] p2: silktosilkclearance=3.94
SilkToSolderMaskClearance SilkToComponentPadClearance [(IsPad or IsFill or IsRegion) and InAnycomponent] p1: minsilkscreentomaskgap=5 clearancetoexposedcopper=TRUE
SilkToSolderMaskClearance "Silk to Solder Mask Opening" [All] p2: minsilkscreentomaskgap=3.94 clearancetoexposedcopper=FALSE
SolderMaskExpansion [All] p1: expansion=1.97 istentingtop=FALSE
SupplyNets "Schematic Supply Nets_1" [InNet('AGND')] p1: voltage=0.000
SupplyNets "Schematic Supply Nets" [InNet('PGND')] p2: voltage=0.000
UnRoutedNet [All] p1: checkbadconnections=TRUE
Width Width_NT [InComponent('NT1')] p1: maxlimit=100 minlimit=99999 preferedwidth=5 toplayer_minwidth=0 midlayer1_minwidth=0 midlayer2_minwidth=0 midlayer3_minwidth=0 midlayer4_minwidth=0 bottomlayer_minwidth=0 minimp=50.000000 maximp=50.000000 favimp=50.000000 checkconnectedcopper=TRUE
Width Width_IC [WithinRoom('Controller')] p2: maxlimit=100 minlimit=5 preferedwidth=5
Width [All] p3: maxlimit=100 minlimit=6 preferedwidth=10 checkconnectedcopper=TRUE
13 further rules are at their usual default settings.

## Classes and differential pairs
component class Label: LBL1
component class Shunt: SH-JP1 SH-JP2 SH-JP3 SH-JP4 SH-JP5 SH-JP6 SH-JP7
component class Header: J2 J3 J4 J5 J6 J7 J8 J9 J10 J11 J12 J13 J14 J15 J16 J17 J19 J20 JP1 JP2 JP3 JP4 JP5 JP6 JP7 JP8 JP9
component class SR088A: C1 C2 C3 C4 C5 C6 C7 C8 C9 C10 C11 C12 C13 C14 C15 C16 C17 C18 C19 C20 C21 C22 C23 C24 C25 C26 C27 C28 C29 C30 C31 C32 C33 C34 C35 C36 C37 C38 C39 C40 C41 C42 C43 C44 C45 C46 C47 C48 C49 C50 C51 C52 C53 C54 C55 J1 J2 J3 J4 J5 J6 J7 J8 J9 J10 J11 J12 J13 J14 J15 J16 J17 J19 J20 J21 J22 J23 J24 J25 J26 J27 JP1 JP2 JP3 JP4 JP5 JP6 JP7 JP8 JP9 L1 NT1 R1 R2 R3 R4 R5 R6 R7 R8 R9 R10 R11 R12 R13 R14 R15 R16 R17 R18 R19 R20 R21 R22 R23 R24 R25 R26 R27 R28 R29 R30 R31 R32 R33 R34 R35 R36 R37 R38 R39 R40 R41 R42 R43 R44 R45 R46 R47 R48 R49 R50 R51 R52 R53 R54 R55 R56 R57 R58 R59 R60 R61 R62 R63 R64 R65 S1 S2 S3 S4 S5 T1 T2 T3 T4 TP1 U1
component class "Mounting Holes": H1 H2 H3 H4
component class SR088A_Hardware: FID1 FID2 FID3 FID4 FID5 FID6 H1 H2 H3 H4 LBL1 Logo5 Logo6 SH-JP1 SH-JP2 SH-JP3 SH-JP4 SH-JP5 SH-JP6 SH-JP7 ZZ1 ZZ2 ZZ3 ZZ4 ZZ5 ZZ6 ZZ7 ZZ8 ZZ9 ZZ10 ZZ11
component class FiducialMark: FID1 FID2 FID3 FID4 FID5 FID6
component class AssemblyNote: ZZ1 ZZ2 ZZ3 ZZ4 ZZ5 ZZ6 ZZ7 ZZ8 ZZ9 ZZ10 ZZ11

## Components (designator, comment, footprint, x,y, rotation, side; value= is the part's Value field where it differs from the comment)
C1 "GCM188D71H105KE36J" FP-GCM188D71H105KE36J_0603-MFG 2379.72,1612.53 r180 bottom value=1µF
C2 "GRM155R62A104ME14D" FP-GRM155R62A104ME14D_0402-S 2433.85,1558.63 r270 top value=100nF
C3 "GRM155R62A104ME14D" FP-GRM155R62A104ME14D_0402-S 2331.85,1561.25 r90 top value=100nF
C4 "GRM155R60J475ME87D" 0402_065S 2294.67,1557.82 r270 top value=4.7uF
C5 "CGA2B2C0G1H101J050BA" 0402S 2381.19,1542.43 r90 top value=100pF
C6 "GRT188R71C334KE01D" FP-GRT188R71C334KE01D_0603-MFG 2200.57,1626.44 r0 bottom value=330nF
C7 "C0603C470J1GACAUTO" 0603S 2225.76,1958.82 r0 bottom value=47pF
C8 "CGA6P3X7R1H475K250AB" 1210_280 2070.78,1449.37 r270 bottom value=4.7uF
C9 "GCD188R71H153KA01D" FP-GCD188R71H153KA01D_0603-MFG 2194.46,1674.34 r0 bottom value=15nF
C10 "GRM1555C1H471JA01D" 0402S 2219.86,1687.24 r270 top value=470pF
C11 "GRM32EC72A106KE05L" FP-GRM32EC72A106KE05L_1210-MFG 2713.35,232.19 r90 bottom
C12 "GRM32EC72A106KE05L" FP-GRM32EC72A106KE05L_1210-MFG 2603.35,232.19 r90 bottom
C13 "GRM32EC72A106KE05L" FP-GRM32EC72A106KE05L_1210-MFG 2493.35,232.19 r90 bottom
C14 "GRM32EC72A106KE05L" FP-GRM32EC72A106KE05L_1210-MFG 2383.35,232.19 r90 bottom
C15 "GRM32EC72A106KE05L" FP-GRM32EC72A106KE05L_1210-MFG 2273.35,232.19 r90 bottom
C16 "EEHZU1H221P" FP-EEHZU1H221P_RADIAL_SMT-MFG 1411.81,988.75 r0 top value=220µF
C17 "EEHZU1H221P" FP-EEHZU1H221P_RADIAL_SMT-MFG 1411.81,504.62 r0 top value=220µF
C18 "GRM155R62A104ME14D" FP-GRM155R62A104ME14D_0402-S 576.82,1232.08 r90 bottom value=100nF
C19 "GRM155R62A104ME14D" FP-GRM155R62A104ME14D_0402-S 1082.17,1232.08 r90 bottom value=100nF
C20 "GRM1885C1H682JA01D" 0603S 2383.95,1407.73 r270 bottom value=6800pF
C21 "GRM155R62A104ME14D" FP-GRM155R62A104ME14D_0402-S 2460.11,1832 r270 top value=100nF
C22 "GRM155R62A104ME14D" FP-GRM155R62A104ME14D_0402-S 2488.2,1832 r270 top value=100nF
C23 "GRM155R62A104ME14D" FP-GRM155R62A104ME14D_0402-S 2516.29,1832 r270 top value=100nF
C24 "GRM155R62A104ME14D" FP-GRM155R62A104ME14D_0402-S 2544.38,1832 r270 top value=100nF
C25 "GRM155R62A104ME14D" FP-GRM155R62A104ME14D_0402-S 2572.48,1832 r270 top value=100nF
C26 "GRM21BD72A225ME01K" FP-GRM21BD72A225ME01K_0805-MFG 2773.95,2074.15 r270 bottom value=2.2µF
C27 "GRM21BD72A225ME01K" FP-GRM21BD72A225ME01K_0805-MFG 2778.45,1661.87 r90 bottom value=2.2µF
C28 "GRM21BD72A225ME01K" FP-GRM21BD72A225ME01K_0805-MFG 2718.37,1686.2 r90 bottom value=2.2µF
C29 "GRM21BD72A225ME01K" FP-GRM21BD72A225ME01K_0805-MFG 2657.19,1709.74 r90 bottom value=2.2µF
C30 "GRM21BD72A225ME01K" FP-GRM21BD72A225ME01K_0805-MFG 2575,1770 r0 bottom value=2.2µF
C31 "GRM21BD72A225ME01K" FP-GRM21BD72A225ME01K_0805-MFG 2575,1830 r0 bottom value=2.2µF
C32 "GRM21BD72A225ME01K" FP-GRM21BD72A225ME01K_0805-MFG 2575,1950 r0 bottom value=2.2µF
C33 "GRM21BD72A225ME01K" FP-GRM21BD72A225ME01K_0805-MFG 2718.37,2045.36 r270 bottom value=2.2µF
C34 "GRM21BD72A225ME01K" FP-GRM21BD72A225ME01K_0805-MFG 2659.11,2014.73 r270 bottom value=2.2µF
C35 "GRM21BD72A225ME01K" FP-GRM21BD72A225ME01K_0805-MFG 2575,1890 r0 bottom value=2.2µF
C36 "GRM32EC72A106KE05L" FP-GRM32EC72A106KE05L_1210-MFG 3175.26,1500.67 r90 bottom
C37 "GRM32EC72A106KE05L" FP-GRM32EC72A106KE05L_1210-MFG 3067.76,1547.36 r90 bottom
C38 "GRM32EC72A106KE05L" FP-GRM32EC72A106KE05L_1210-MFG 2964.59,1584.03 r90 bottom
C39 "GRM32EC72A106KE05L" FP-GRM32EC72A106KE05L_1210-MFG 2859.18,1622.52 r90 bottom
C40 "GRM32EC72A106KE05L" FP-GRM32EC72A106KE05L_1210-MFG 3163.95,2258.98 r270 bottom
C41 "GRM32EC72A106KE05L" FP-GRM32EC72A106KE05L_1210-MFG 3060.91,2208.89 r270 bottom
C42 "GRM32EC72A106KE05L" FP-GRM32EC72A106KE05L_1210-MFG 2957.3,2155.36 r270 bottom
C43 "GRM32EC72A106KE05L" FP-GRM32EC72A106KE05L_1210-MFG 2853.96,2106.57 r270 bottom
C44 "EEHZU1J151P" FP-EEHZU1J151P_RADIAL_SMT-MFG 3624.25,2495.23 r180 top value=150µF
C45 "EEHZU1J151P" FP-EEHZU1J151P_RADIAL_SMT-MFG 3624.25,2049.37 r180 top value=150µF
C46 "EEHZU1J151P" FP-EEHZU1J151P_RADIAL_SMT-MFG 3624.25,1603.52 r180 top value=150µF
C47 "EEHZU1J151P" FP-EEHZU1J151P_RADIAL_SMT-MFG 3624.25,1157.66 r180 top value=150µF
C48 "GRM155R62A104ME14D" FP-GRM155R62A104ME14D_0402-S 4415.69,1225.73 r90 bottom value=100nF
C49 "GRM155R62A104ME14D" FP-GRM155R62A104ME14D_0402-S 3926.95,1234.4 r90 bottom value=100nF
C50 "GRT188R71C334KE01D" FP-GRT188R71C334KE01D_0603-MFG 1823.77,2780.76 r180 bottom value=330nF
C51 "GRM155R62A104ME14D" FP-GRM155R62A104ME14D_0402-S 2316.23,2817.84 r90 bottom value=100nF
C52 "GRM1885C1H332JA01D" 0603S 526.08,2681.57 r180 bottom value=3300pF
C53 "GRM1885C1H332JA01D" 0603S 525.51,2511.47 r180 bottom value=3300pF
C54 "GRM1885C1H332JA01D" 0603S 376.08,2681.57 r180 bottom value=3300pF
C55 "GRM1885C1H332JA01D" 0603S 376.08,2511.47 r180 bottom value=3300pF
FID1 "Fiducial" Fiducial10-20 484.88,281.66 r0 top
FID2 "Fiducial" Fiducial10-20 4480.32,243.92 r0 top
FID3 "Fiducial" Fiducial10-20 4640,3400 r0 top
FID4 "Fiducial" Fiducial10-20 4478.35,246.06 r180 bottom
FID5 "Fiducial" Fiducial10-20 496.12,236.22 r180 bottom
FID6 "Fiducial" Fiducial10-20 4645.39,3412.44 r180 bottom
H1 "NY PMS 440 0025 PH" "NY PMS 440 0025 PH" 4808,3598 r0 top
H2 "NY PMS 440 0025 PH" "NY PMS 440 0025 PH" 202,3598 r0 top
H3 "NY PMS 440 0025 PH" "NY PMS 440 0025 PH" 202,202 r0 top
H4 "NY PMS 440 0025 PH" "NY PMS 440 0025 PH" 4808,202 r0 top
J1 "Header_5x2" CONN_2510-6002 4825,2925 r90 top
J2 "61300311121" WURTH_61300311121 850,2880 r270 top
J3 "61300311121" WURTH_61300311121 1200,2880 r270 top
J4 "61300311121" WURTH_61300311121 1550,2880 r270 top
J5 "61300311121" WURTH_61300311121 2000,2880 r270 top
J6 "61300211121" WURTH_61300211121 2992.43,3015 r270 top
J7 "61300211121" WURTH_61300211121 4119.22,3015 r270 top
J8 "61300211121" WURTH_61300211121 2165.35,406.75 r90 top
J9 "PEC08SAAN" SULLINS_PEC08SAAN 1005,1235 r270 top
J10 "61300211121" WURTH_61300211121 478.41,1229.64 r270 top
J11 "61300311121" WURTH_61300311121 200,2880 r270 top
J12 "61300311121" WURTH_61300311121 350,2880 r270 top
J13 "61300311121" WURTH_61300311121 500,2880 r270 top
J14 "61300311121" WURTH_61300311121 650,2880 r270 top
J15 "61300211121" WURTH_61300211121 690,3266 r270 top
J16 "61300211121" WURTH_61300211121 1115,3266 r270 top
J17 "61300211121" WURTH_61300211121 1540,3265.99 r270 top
J19 "PEC08SAAN" SULLINS_PEC08SAAN 4004.33,1235 r270 top
J20 "61300211121" WURTH_61300211121 4500,1223.71 r270 top
J21 "108-0740-001" Johnson_108-0740-001 510,1735 r0 top
J22 "108-0740-001" Johnson_108-0740-001 510,735 r0 top
J23 "108-0740-001" Johnson_108-0740-001 4500,1735 r0 top
J24 "108-0740-001" Johnson_108-0740-001 4500,735 r0 top
J25 "MMCX-J-P-H-ST-TH1" Samtec_MMCX-J-P-H-ST-TH1 690,3560 r270 top
J26 "MMCX-J-P-H-ST-TH1" Samtec_MMCX-J-P-H-ST-TH1 1115,3560 r270 top
J27 "MMCX-J-P-H-ST-TH1" Samtec_MMCX-J-P-H-ST-TH1 1540,3560 r270 top
JP1 "61300211121" WURTH_61300211121 1440.54,1793.81 r0 top
JP2 "61300311121" WURTH_61300311121 1000,2880 r270 top
JP3 "61300311121" WURTH_61300311121 1350,2880 r270 top
JP4 "61300311121" WURTH_61300311121 1700,2880 r270 top
JP5 "61300311121" WURTH_61300311121 2150,2880 r270 top
JP6 "61300311121" WURTH_61300311121 3280,2985 r0 top
JP7 "61300311121" WURTH_61300311121 4405,2985 r0 top
JP8 "61300311121" WURTH_61300311121 2030.69,1885.7 r90 top
JP9 "61300111121" WURTH_61300111121 2250,2880 r0 top
L1 "XGL1712-332MED" FP-XGL1712-332MED_SMT2_17MM2_18MM2-MFG 2487,950 r90 bottom value=3.3uH
LBL1 "THT-14-423-10" Label_650x200 3744.34,324.68 r180 top
Logo5 "CAUTION HOT SURFACE" IEC_HotSurface_Small 2708.49,1690.21 r0 top
Logo6 "CAUTION HOT SURFACE" IEC_HotSurface_Small 2487,530.61 r0 top
NT1 "Net-Tie" Net-Tie_6x8mil 2350.75,1642.02 r217 top net-tie
R1 "KRL2012E-M-R004-F-T5" FP-KRL2012E-M-R004-F-T5_2012-MFG 2557.69,415.31 r90 bottom value=4m
R2 "KRL2012E-M-R004-F-T5" FP-KRL2012E-M-R004-F-T5_2012-MFG 2424.48,413.65 r90 bottom value=4m
R3 "KRL6432E-M-R003-F-T1" 2512_WIDE 2628.16,413.96 r90 bottom value=0.003
R4 "KRL6432E-M-R003-F-T1" 2512_WIDE 2353.16,413.96 r90 bottom value=0.003
R5 "ERJ-3GEY0R00V" 0603S 1919.83,1412.03 r270 bottom value=0
R6 "ERJ-3GEY0R00V" 0603S 1978.73,1412.03 r270 bottom value=0
R7 "CRCW060378K7FKEA" 0603S 2225.76,2013.92 r0 bottom value=78.7k
R8 "CRCW06033K40FKEA" 0603S 2134,1572.18 r0 bottom value=3.40k
R9 "CRCW060320K0FKEA" 0603S 2129.01,1645.62 r90 bottom value=20.0k
R10 "CRCW121810R0FKEK" 1218 2253.51,1427.22 r270 bottom value=10.0
R11 "CRCW060340K2FKEA" 0603S 2037.95,1701.13 r180 bottom value=40.2k
R12 "CRCW0603100KFKEA" 0603S 886.15,3062.08 r180 bottom value=100k
R13 "RMCF0603ZT0R00" 0603S 1823.77,2979.26 r0 bottom value=0
R14 "CRCW060375K0FKEA" 0603S 2363.46,2935.16 r90 bottom value=75.0k
R15 "RC0603FR-0739KL" 0603S 2363.46,2817.01 r270 bottom value=39.0k
R16 "CRCW060324K9FKEA" 0603S 1910,3280 r90 top value=24.9k
R17 "CRCW060331K6FKEA" 0603S 1965,3280 r90 top value=31.6k
R18 "CRCW060340K2FKEA" 0603S 2020,3280 r90 top value=40.2k
R19 "CRCW060348K7FKEA" 0603S 2075,3280 r270 top value=48.7k
R20 "CRCW060361K9FKEA" 0603S 2130,3280 r90 top value=61.9k
R21 "CRCW060375K0FKEA" 0603S 2185,3280 r90 top value=75.0k
R22 "CRCW060390K9FKEA" 0603S 2240,3280 r90 top value=90.9k
R23 "CRCW0603110KFKEA" 0603S 2295,3280 r270 top value=110k
R24 "RMCF0603ZT0R00" 0603S 2565,3280 r270 top value=0
R25 "CRCW0603511RFKEA" 0603S 2620,3280 r90 top value=511
R26 "CRCW06031K30FKEA" 0603S 2675,3280 r270 top value=1.30k
R27 "CRCW06031K87FKEA" 0603S 2730,3280 r90 top value=1.87k
R28 "CRCW06032K74FKEA" 0603S 2785,3280 r270 top value=2.74k
R29 "CRCW06033K83FKEA" 0603S 2840,3280 r90 top value=3.83k
R30 "CRCW06035K11FKEA" 0603S 2895,3280 r90 top value=5.11k
R31 "CRCW06036K49FKEA" 0603S 2950,3280 r90 top value=6.49k
R32 "CRCW06038K25FKEA" 0603S 3035,3280 r90 top value=8.25k
R33 "CRCW060310K5FKEA" 0603S 3090,3280 r90 top value=10.5k
R34 "CRCW060313K3FKEA" 0603S 3145,3280 r90 top value=13.3k
R35 "CRCW060316K2FKEA" 0603S 3200,3280 r270 top value=16.2k
R36 "CRCW060320K5FKEA" 0603S 3255,3280 r90 top value=20.5k
R37 "CRCW060324K9FKEA" 0603S 3310,3280 r90 top value=24.9k
R38 "CRCW060330K1FKEA" 0603S 3365,3280 r90 top value=30.1k
R39 "CRCW060336K5FKEA" 0603S 3420,3280 r270 top value=36.5k
R40 "RMCF0603ZT0R00" 0603S 3690,3280 r270 top value=0
R41 "CRCW0603511RFKEA" 0603S 3745,3280 r90 top value=511
R42 "CRCW06031K30FKEA" 0603S 3800,3280 r270 top value=1.30k
R43 "CRCW06031K87FKEA" 0603S 3855,3280 r90 top value=1.87k
R44 "CRCW06032K74FKEA" 0603S 3910,3280 r270 top value=2.74k
R45 "CRCW06033K83FKEA" 0603S 3965,3280 r90 top value=3.83k
R46 "CRCW06035K11FKEA" 0603S 4020,3280 r90 top value=5.11k
R47 "CRCW06036K49FKEA" 0603S 4075,3280 r90 top value=6.49k
R48 "CRCW06038K25FKEA" 0603S 4160,3280 r90 top value=8.25k
R49 "CRCW060310K5FKEA" 0603S 4215,3280 r90 top value=10.5k
R50 "CRCW060313K3FKEA" 0603S 4270,3280 r90 top value=13.3k
R51 "CRCW060316K2FKEA" 0603S 4325,3280 r270 top value=16.2k
R52 "CRCW060320K5FKEA" 0603S 4380,3280 r90 top value=20.5k
R53 "CRCW060324K9FKEA" 0603S 4435,3280 r90 top value=24.9k
R54 "CRCW060330K1FKEA" 0603S 4490,3280 r90 top value=30.1k
R55 "CRCW060336K5FKEA" 0603S 4545,3280 r270 top value=36.5k
R56 "RMCF0603ZT0R00" 0603S 2194.11,1727.2 r180 bottom value=0
R57 "RMCF0603ZT0R00" 0603S 2225.76,2066.52 r180 bottom value=0
R58 "RMCF0603ZT0R00" 0603S 2103.92,1811.98 r270 bottom value=0
R59 "RMCF0603ZT0R00" 0603S 2104.86,1906.46 r270 bottom value=0
R60 "CRCW060353K6FKEA" 0603S 2219.41,1561.06 r90 bottom value=53.6k
R61 "RMCF0603ZT0R00" 0603S 2037.95,1630.21 r180 bottom value=0
R62 "ERJ-3GEY0R00V" 0603S 556.33,2595.95 r90 bottom value=0
R63 "ERJ-3GEY0R00V" 0603S 406.4,2595.95 r90 bottom value=0
R64 "RMCF0603ZT0R00" 0603S 2038.15,1575.97 r180 bottom value=0
R65 "CRCW060366K5FKEA" 0603S 4305.3,1223.71 r90 bottom value=66.5k
S1 "218-8LPST" SW_218-8LP 2100,3520 r90 top
S2 "218-8LPST" SW_218-8LP 2758.9,3520 r90 top
S3 "218-8LPST" SW_218-8LP 3225,3520 r90 top
S4 "218-8LPST" SW_218-8LP 3883.9,3520 r90 top
S5 "218-8LPST" SW_218-8LP 4350,3520 r90 top
SH-JP1 "SPC02SYAN" SPC02SYAN 1438.22,1795.1 r180 top value=1x2
SH-JP2 "SPC02SYAN" SPC02SYAN 995.36,2831.82 r90 top value=1x2
SH-JP3 "SPC02SYAN" SPC02SYAN 1347.19,2830.58 r90 top value=1x2
SH-JP4 "SPC02SYAN" SPC02SYAN 1696.86,2832.14 r90 top value=1x2
SH-JP5 "SPC02SYAN" SPC02SYAN 2195.63,2880.23 r180 top value=1x2
SH-JP6 "SPC02SYAN" SPC02SYAN 3230.49,2984.82 r180 top value=1x2
SH-JP7 "SPC02SYAN" SPC02SYAN 4356.09,2984.82 r180 top value=1x2
T1 "CXS70-14-C" Panduit_CXS70-14-C 510,1735 r0 top
T2 "CXS70-14-C" Panduit_CXS70-14-C 510,735 r0 top
T3 "CXS70-14-C" Panduit_CXS70-14-C 4500,1735 r180 top
T4 "CXS70-14-C" Panduit_CXS70-14-C 4500,735 r180 top
TP1 "RCU-0C" TE_RCU 2537.14,1539.19 r180 top
U1 "LMG5126VBTT" VBT0022A-MFG 2439.61,1700 r90 top
ZZ1 "This Assembly Note is for PCB labels only" AssemblyNoteLabel 150,3950 r0 top
ZZ2 "These assemblies are ESD sensitive, ESD precautions shall be observed." AssemblyNote 150,4050 r0 top
ZZ3 "These assemblies must be clean and free from flux and all contaminants. Use of no clean flux is not acceptable." AssemblyNote 150,4150 r0 top
ZZ4 "These assemblies must comply with workmanship standards IPC-A-610 Class 2, unless otherwise specified." AssemblyNote 150,4250 r0 top
ZZ5 "Install Shunt Jumper SH-J1 onto J1" AssemblyNote 150,4350 r0 top
ZZ6 "Install Shunt Jumper SH-J2 onto JP2 pins 2-3" AssemblyNote 150,4450 r0 top
ZZ7 "Install Shunt Jumper SH-J3 onto JP3 pins 2-3" AssemblyNote 150,4550 r0 top
ZZ8 "Install Shunt Jumper SH-J4 onto JP4 pins 2-3" AssemblyNote 150,4650 r0 top
ZZ9 "Install Shunt Jumper SH-J5 onto JP5-JP9" AssemblyNote 150,4750 r0 top
ZZ10 "Install Shunt Jumper SH-J6 onto JP6 pins 1-2" AssemblyNote 150,4850 r0 top
ZZ11 "Install Shunt Jumper SH-J7 onto JP7 pins 1-2" AssemblyNote 150,4950 r0 top

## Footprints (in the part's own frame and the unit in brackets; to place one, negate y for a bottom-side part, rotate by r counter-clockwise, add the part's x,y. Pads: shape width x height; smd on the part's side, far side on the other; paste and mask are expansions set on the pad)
0402_065S [mil] "Based on C0402S footprint from PADS legacy"
  rect 15x24 smd: 1(-20,0) 2(20,0)
  body extent -22,-12 22,12, height 26
0402S [mil] "Based on C0402S footprint from PADS legacy"
  rect 15x24 smd: 1(-20,0) 2(20,0)
  body extent -22,-12 22,12, height 24
0603S [mil]
  rect 20x35 smd: 1(-30,0) 2(30,0)
  body extent -34,-19 34,19, height 39
1210_280 [mm] "SMD, 2-Leads, Body 3.6x2.8mm, Height 2.8mm"
  rect 1.1x2.2 smd: 1(-1.65,0) 2(1.65,0)
  silkscreen extent -0.84,-1.4 0.84,1.4, body extent -1.8,-1.4 1.8,1.4, height 2.8
1218 [mil] "Vishay recommended land pattern for 1218, document number 20008 revision 13-Oct-08"
  rrect10% 40x187 smd: 1(-59,0) 2(59,0)
  body extent -65,-93 65,93, height 24
2512_WIDE [mil] "Ohmite recommended land pattern"
  rect 35x259.84 smd mask+0: 1(-64.99,0) 2(64.99,0)
  silkscreen extent -32,-131 32,132, body extent -65,-128 65,128, height 28
AssemblyNote [mil] "Assembly Note"
AssemblyNoteLabel [mil] "Assembly Note for PCB Labels"
CONN_2510-6002 [mm] "3M 2500 series TS-0770-L December 15, 2011"
  rect 1.65x1.65 hole 1.016 mask+0: 1(-5.08,-1.27)
  round 1.65 hole 1.016 mask+0: 2(-5.08,1.27) 3(-2.54,-1.27) 4(-2.54,1.27) 5(0,-1.27) 6(0,1.27) 7(2.54,-1.27) 8(2.54,1.27) 9(5.08,-1.27) 10(5.08,1.27)
  silkscreen extent -10.01,-4.17 10.01,4.47, body extent -10.01,-4.11 10.01,4.52, height 9.92
Fiducial10-20 [mm]
  round 1 smd mask+0.5: 1(0,0)
  Top Layer keep-out circle w1.178: c0,0 r0.5
FP-EEHZU1H221P_RADIAL_SMT-MFG [mm]
  rrect5% 4.1x2 smd paste+0 mask+0: 1(-4.35,0) 2(4.35,0)
  silkscreen extent -7.07,-5.25 5.25,5.25, body extent -6.65,-5.5 6.65,5.5, height 0.25
FP-EEHZU1J151P_RADIAL_SMT-MFG [mm]
  rrect5% 4.1x2 smd paste+0 mask+0: 1(-4.35,0) 2(4.35,0)
  silkscreen extent -7.07,-5.25 5.25,5.25, body extent -6.65,-5.5 6.65,5.5, height 0.25
FP-GCD188R71H153KA01D_0603-MFG [mm]
  rrect15% 0.65x0.7 smd paste+0 mask+0: 1(-0.675,0) 2(0.675,0)
  body extent -0.8,-0.4 0.8,0.4, height 0.9
FP-GCM188D71H105KE36J_0603-MFG [mm]
  rrect13% 0.75x0.9 smd paste+0 mask+0: 1(-0.775,0) 2(0.775,0)
  silkscreen extent 0,-0.5 0,0.5, body extent -0.8,-0.4 0.8,0.4, height 1
FP-GRM21BD72A225ME01K_0805-MFG [mm]
  rrect14% 0.7x1.3 smd paste+0 mask+0: 1(-0.95,0) 2(0.95,0)
  body extent -1,-0.63 1,0.63, height 1.45
FP-GRM32EC72A106KE05L_1210-MFG [mm]
  rrect9% 1.1x2.05 smd paste+0 mask+0: 1(-1.65,0) 2(1.65,0)
  body extent -1.6,-1.25 1.6,1.25, height 2.7
FP-GRM155R62A104ME14D_0402-S [mm]
  rrect25% 0.4x0.5 smd paste+0 mask+0: 1(-0.4,0) 2(0.4,0)
  body extent -0.7,-0.37 0.7,0.38, height 0.25
FP-GRT188R71C334KE01D_0603-MFG [mm]
  rrect15% 0.65x0.7 smd paste+0 mask+0: 1(-0.675,0) 2(0.675,0)
  body extent -0.8,-0.4 0.8,0.4, height 0.9
FP-KRL2012E-M-R004-F-T5_2012-MFG [mm]
  rrect14% 0.7x2.2 smd paste+0 mask+0: 1(-0.65,0) 2(0.65,0)
  silkscreen extent -0.77,-1.53 0.67,1.53, body extent -0.63,-1 0.63,1, height 0.7
FP-XGL1712-332MED_SMT2_17MM2_18MM2-MFG [mm]
  rrect3% 3.8x15.1 smd paste+0 mask+0: 1(-5.93,0) 2(5.93,0)
  silkscreen extent -9.47,-9.2 8.7,9.2, body extent -8.6,-9.1 8.6,9.1, height 12
IEC_HotSurface_Small [mil]
  silkscreen extent -107,-93 107,92
Johnson_108-0740-001 [mm] "Banana Jack Uninsulated Standard Type"
  round 12 hole 6.858: 1(0,0)
  body extent -4.77,-5.43 4.75,5.57, height 2.39
Label_650x200 [mil] "Thermal Transfer Label"
  round 1 on Mech13: 0(0,0)
  silkscreen extent -325,-100 325,100, body extent -325,-100 325,100, height 1
Net-Tie_6x8mil [mil]
  rect 14x6 smd paste-5 mask-5: 1(-7,0) 2(7,0)
"NY PMS 440 0025 PH" [mm] "4-40 nylon screw and mounting hole"
  round 8 hole 3.2: 1(0,0)
  body extent -3.3,-3.3 3.3,3.3, height 2.69
Panduit_CXS70-14-C [mil] "Panduit"
  rect 770x500 hole 270 copper offset -74.8,0 paste-99999: 1(0,0)
  body extent -960,-250 310,250, height 684
Samtec_MMCX-J-P-H-ST-TH1 [mm] "Connector, MMCX, TH"
  round 1.2 hole 0.84: 1(0,0) 2(-1.27,1.27) 3(1.27,1.27) 4(1.27,-1.27) 5(-1.27,-1.27)
  silkscreen extent -1.75,-1.75 1.75,1.75, body extent -1.75,-1.75 1.75,1.75, height 4.35
SPC02SYAN [mil] "SULLINS"
  round 1 on Mech3: 0(0,0)
  body extent -98,-47 99,47, height 366
SULLINS_PEC08SAAN [mm] "SULLINS"
  rect 1.65x1.65 hole 1: 1(-8.89,0)
  round 1.65 hole 1: 2(-6.35,0) 3(-3.81,0) 4(-1.27,0) 5(1.27,0) 6(3.81,0) 7(6.35,0) 8(8.89,0)
  silkscreen extent -10.67,-1.4 10.29,1.52, body extent -10.29,-1.33 10.29,1.33, height 8.38
SW_218-8LP [mm] "SMD, 16-Leads, Body 11.33x5.8mm, Pitch 1.27mm"
  rect 1.27x0.76 smd: 1(-3.81,4.445) 2(-3.81,3.175) 3(-3.81,1.905) 4(-3.81,0.635) 5(-3.81,-0.635) 6(-3.81,-1.905) 7(-3.81,-3.175) 8(-3.81,-4.445) 9(3.81,-4.445) 10(3.81,-3.175) 11(3.81,-1.905) 12(3.81,-0.635) 13(3.81,0.635) 14(3.81,1.905) 15(3.81,3.175) 16(3.81,4.445)
  silkscreen extent -2.9,-5.67 2.9,5.9, body extent -4.22,-5.66 4.22,5.66, height 2.62
TE_RCU [mm] "SMD, 1-Leads, Body 1.6x0.8mm"
  rrect8% 2.4x1.2 smd: 1(0,0)
  body extent -0.8,-0.45 0.8,0.45, height 1.15
VBT0022A-MFG [mm] "Recommended Land Pattern"
  round 0.234 smd paste+0 mask+0: 1(-1.837,2.762)
  rrect40% 0.7x0.25 smd paste+0 mask+0: 2(-2.1,2.125) 3(-2.1,1.625) 4(-2.1,1.125) 5(-2.1,0.625) 6(-2.1,0.125) 10(2.1,0.125) 11(2.1,0.625) 12(2.1,1.125) 13(2.1,1.625) 14(2.1,2.125)
  rrect25% 0.8x2.35 smd paste-1000 mask-1000: 7(-2.1,-1.675) 9(2.1,-1.675)
  rrect10% 2x3.15 smd paste-1000 mask-1000: 8(0,-1.675)
  round 0.265 smd paste+0 mask+0: 15(1.875,2.675)
  rrect40% 0.25x0.7 smd paste+0 mask+0: 16(1.25,2.85) 17(0.75,2.85) 18(0.25,2.85) 19(-0.25,2.85) 20(-0.75,2.85) 21(-1.25,2.85)
  rrect10% 2.6x2.1 smd paste-1000 mask-1000: 22(0,1.15)
  Top Layer region: -2.4,2.5 -2.419,2.504 -2.435,2.515 -2.446,2.531 -2.45,2.55 -2.45,2.55 -2.45,2.7 -2.443,2.725 -2.425,2.743 -2.4,2.75 -2.4,2.75 -2.05,2.75 -2.012,2.758 -1.979,2.779 -1.958,2.812 -1.95,2.85 -1.95,2.85 -1.95,3.15 -1.943,3.175 -1.925,3.193 -1.9,3.2 -1.9,3.2 -1.75,3.2 -1.725,3.193 -1.707,3.175 -1.7,3.15 -1.7,3.15 -1.7,2.55 -1.704,2.531 -1.715,2.515 -1.731,2.504 -1.75,2.5 -1.75,2.5
  Top Layer region: 2.4,2.5 2.419,2.504 2.435,2.515 2.446,2.531 2.45,2.55 2.45,2.55 2.45,2.7 2.446,2.719 2.435,2.735 2.419,2.746 2.4,2.75 2.4,2.75 2.05,2.75 2.012,2.758 1.979,2.779 1.958,2.812 1.95,2.85 1.95,2.85 1.95,3.15 1.946,3.169 1.935,3.185 1.919,3.196 1.9,3.2 1.9,3.2 1.75,3.2 1.725,3.193 1.707,3.175 1.7,3.15 1.7,3.15 1.7,2.55 1.704,2.531 1.715,2.515 1.731,2.504 1.75,2.5 1.75,2.5
  silkscreen extent -1.99,3.74 -1.74,3.99, body extent -2.25,-3 2.25,3, height 0.85
WURTH_61300111121 [mm] "Header, 2.54 mm, 1x1, TH"
  rect 1.65x1.65 hole 1.15: 1(0,0)
  body extent -1.27,-1.27 1.27,1.27, height 8.54
WURTH_61300211121 [mm] "Header, 2.54mm, 2x1, TH"
  rrect50% 1.65x1.65 hole 1.15: 1(-1.27,0)
  round 1.65 hole 1.15: 2(1.27,0)
  body extent -2.54,-1.27 2.54,1.27, height 8.54
WURTH_61300311121 [mm] "Header, 2.54mm, 3x1, TH"
  rrect50% 1.65x1.65 hole 1.15: 1(-2.54,0)
  round 1.65 hole 1.15: 2(0,0) 3(2.54,0)
  body extent -3.81,-1.27 3.81,1.27, height 8.54

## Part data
C1: library part CMP-0122291-1, "1 µF ±10% 50V Ceramic Capacitor X7T 0603 (1608 Metric)", Digikey Part Number=490-GCM188D71H105KE36JCT-ND, Manufacturer=Murata, Mouser Part Number=81-GCM188D71H105KE6J, Operating Temperature Range="-55°C to +125°C", TempCo=+22/-33%, Temperature Characteristic=X7T, Tolerance_%=10%, ValueDisplayed=1uF
C2 C3 C18 C19 C21 C22 C23 C24 C25 C48 C49 C51: library part CMP-0093748-2, "Chip Multilayer Ceramic Capacitors for General Purpose, 0402, 0.10uF, X5R, 15%, 20%, 100V", Manufacturer=Murata, Operating Temperature Range="-55°C to +85°C", TempCo=15%, Temperature Characteristic=X5R, Tolerance_%=20%, ValueDisplayed=0.10uF
C4: library part CMP-0006553-3, "CAP, CERM, 4.7 uF, 6.3 V, +/- 20%, X5R, 0402", Cap_Case=0402, Manufacturer=MuRata, Supplier Part Number 1=490-5408-1-ND, TempCo=X5R, Tolerance_%=20%, Value1="0.009 ohm", Value2=6.3V, ValueDisplayed=4.7uF
C5: library part CMP-0006308-2, "CAP, CERM, 100 pF, 50 V, +/- 5%, C0G/NP0, AEC-Q200 Grade 1, 0402", Cap_Case=0402, Manufacturer=TDK, Supplier Part Number 1=445-5596-1-ND, TempCo=C0G/NP0, Tolerance_%=5%, Value1=Unknown, Value2=50V, ValueDisplayed=100pF
C6 C50: library part CMP-0121474-1, "Multi-Layer Ceramic Capacitor 330nF 16V X7R ±10% 0603 Paper T/R", Manufacturer=Murata, Operating Temperature Range="-55°C to +125°C", TempCo=15%, Temperature Characteristic=X7R, Tolerance_%=10%, ValueDisplayed=330nF
C7: library part CMP-0085572-1, "CAP, CERM, 47 pF, 100 V,+/- 5%, C0G/NP0, AEC-Q200 Grade 1, 0603", Cap_Case=0603, Manufacturer=Kemet, TempCo=C0G/NP0, Tolerance_%=5%, Value2=100V, ValueDisplayed=47pF
C8: library part CMP-0009162-2, "CAP, CERM, 4.7 uF, 50 V, +/- 10%, X7R, AEC-Q200 Grade 1, 1210", Cap_Case=1210_280, Manufacturer=TDK, Supplier Part Number 1=445-6999-1-ND, TempCo=X7R, Tolerance_%=10%, Value1="0.003166 ohm", Value2=50V, ValueDisplayed=4.7uF
C9: library part CMP-0121472-1, "Chip Multilayer Ceramic Capacitors for Automotive, 0603, 15000pF, X7R, 15%, 10%, 50V, Grade 1", Manufacturer=Murata, Operating Temperature Range="-55°C to +125°C", TempCo=15%, Temperature Characteristic=X7R, Tolerance_%=10%, ValueDisplayed=15000pF
C10: library part CMP-0006470-2, "CAP, CERM, 470 pF, 50 V, +/- 5%, C0G/NP0, 0402", Cap_Case=0402, Manufacturer=MuRata, Supplier Part Number 1=490-1297-1-ND, TempCo=C0G/NP0, Tolerance_%=5%, Value1=Unknown, Value2=50V, ValueDisplayed=470pF
C11 C12 C13 C14 C15 C36 C37 C38 C39 C40 C41 C42 C43: library part CMP-0087970-1, "10µF ±10% 100V Ceramic Capacitor X7S 1210 (3225 Metric)", Manufacturer=Murata, TempCo=22%, Tolerance_%=10%, ValueDisplayed=10uF
C16 C17: library part CMP-0120360-1, "Aluminum Hybrid Polymer Capacitors 220uF 20% 50V Life 4000Hours AEC-Q200 RADIAL SMT", Leakage Current=110uA, Manufacturer=Panasonic, Operating Temperature Range="-55°C to +135°C", Tolerance_%=20%, ValueDisplayed=220uF
C20: library part CMP-0078296-1, "CAP, CERM, 6800 pF, 50 V,+/- 5%, C0G/NP0, 0603", Cap_Case=0603, Manufacturer=MuRata, Supplier Part Number 1=490-11477-1-ND, TempCo=C0G/NP0, Tolerance_%=5%, Value2=50V, ValueDisplayed=6800pF
C26 C27 C28 C29 C30 C31 C32 C33 C34 C35: library part CMP-0096278-1, "Chip Multilayer Ceramic Capacitor for General Purpose 2.2uF ±20% 100V X7T SMD 0805", Digikey Part Number=490-GRM21BD72A225ME01KCT-ND, Manufacturer=Murata, Mouser Part Number=81-GRM21BD72A225ME1K, Operating Temperature Range="-55°C to +125°C", TempCo=+22/-33%, Temperature Characteristic=X7T, Tolerance_%=20%, ValueDisplayed=2.2uF
C44 C45 C46 C47: library part CMP-0120392-1, "Aluminum Hybrid Polymer Capacitors 150uF 20% 63V Life 4000Hours AEC-Q200 RADIAL SMT", Leakage Current=94.5uA, Manufacturer=Panasonic, Operating Temperature Range="-55°C to +135°C", Tolerance_%=20%, ValueDisplayed=150uF
C52 C53 C54 C55: library part CMP-0007210-4, "CAP, CERM, 3300 pF, 50 V, +/- 5%, C0G/NP0, 0603", Cap_Case=0603, Manufacturer=MuRata, Supplier Part Number 1=GRM1885C1H332JA01D-ND, TempCo=C0G/NP0, Tolerance_%=5%, Value1=Unknown, Value2=50V, ValueDisplayed=3300pF
FID1 FID2 FID3 FID4 FID5 FID6: library part CMP-0077181-1, "Fiducial mark.  There is nothing to buy or mount.", Manufacturer=N/A
H1 H2 H3 H4: library part CMP-0003617-1, "Machine Screw, Round, #4-40 x 1/4, Nylon, Philips panhead", Manufacturer="B&F Fastener Supply", Supplier Part Number 1=H542-ND
J1: library part CMP-0055448-2, "Header (shrouded), 100mil, 5x2, High-Temperature, Gold, TH", Manufacturer=3M, PartNumber=N2510-6002-RB, Supplier Part Number 1=MHC10K-ND
J2 J3 J4 J5 J11 J12 J13 J14 JP2 JP3 JP4 JP5 JP6 JP7 JP8: library part CMP-0054796-4, "Header, 2.54 mm, 3x1, Gold, TH", Manufacturer="Wurth Elektronik", Supplier Part Number 1=732-5316-ND
J6 J7 J8 J10 J15 J16 J17 J20 JP1: library part CMP-0054794-2, "Header, 2.54 mm, 2x1, Gold, TH", Color=Black, Manufacturer="Wurth Elektronik", Supplier Part Number 1=732-5315-ND
J9 J19: library part CMP-0054563-1, "Header, 100mil, 8x1, Tin, TH", Color=Black, Current_A=3A, Manufacturer="Sullins Connector Solutions", Supplier Part Number 1=S1012E-08-ND, Voltage_V=1.8kV
J21 J22 J23 J24: library part CMP-0055387-2, "Standard Banana Jack, Uninsulated, 15A", Manufacturer="Cinch Connectivity", Supplier Part Number 1=J147-ND
J25 J26 J27: library part CMP-0075554-1, "Connector, MMCX 50 ohm, TH", Manufacturer=Samtec, Supplier Part Number 1=88K0549
JP9: library part CMP-0054792-1, "Header, 2.54 mm, 1x1, Gold, TH", Manufacturer="Wurth Elektronik", Supplier Part Number 1=732-5314-ND
L1: library part CMP-0120649-1, "Shielded Power Inductors 3.3µH ±20% 41.7A 1.9mOhms", Manufacturer=Coilcraft, Operating Temperature Range=to, Self Resonant Frequency=15MHz, Test Frequency=100kHz, Tolerance_%=20%
LBL1: library part CMP-0003625-1, "Thermal Transfer Printable Labels, 0.650\" W x 0.200\" H - 10,000 per roll", Manufacturer=Brady, Supplier Part Number 1=97C5133
Logo5 Logo6: library part CMP-0074837-2, "IEC 61010-1 Hot Surface Warning", Manufacturer="Texas Instruments"
NT1: library part CMP-0078142-6, "Single point connection between nets.", Manufacturer=N/A
R1 R2: library part CMP-0090660-1, "4 mOhms ±1% 1W Chip Resistor Wide 0805 (2012 Metric), 0508 Automotive AEC-Q200, Current Sense Metal Foil", Digikey Part Number=408-1594-1-ND, Manufacturer=Susumu, Mouser Part Number=754-KRL2012EMR004FT5, Operating Temperature Range="-55°C to +155°C", Power_W=1W, TempCo=50ppm/°C, Tolerance_%=1%
R3 R4: library part CMP-0015106-2, "RES, 0.003, 1%, 3 W, AEC-Q200 Grade 0, 2512 WIDE", Manufacturer="Susumu Co Ltd", Power_W=3W, Supplier Part Number 1=408-1613-1-ND, TempCo="50 ppm/C", Tolerance_%=1%, Value_Code=3L000, ValueDisplayed=0.003
R5 R6 R62 R63: library part CMP-0025874-4, "RES, 0, 5%, 0.1 W, AEC-Q200 Grade 0, 0603", Manufacturer=Panasonic, Power_W=100mW, Supplier Part Number 1=P0.0GCT-ND, TempCo="600 ppm/C", Tolerance_%=5%, Value2=0.1W, Value_Code=0000, ValueDisplayed=0
R7: library part CMP-0022597-4, "RES, 78.7 k, 1%, 0.1 W, AEC-Q200 Grade 0, 0603", Manufacturer=Vishay-Dale, Power_W=100mW, Supplier Part Number 1=541-78.7KHCT-ND, TempCo="100 ppm/C", Tolerance_%=1%, Value2=0.1W, Value_Code=78k7, ValueDisplayed=78.7k
R8: library part CMP-0022376-4, "RES, 3.40 k, 1%, 0.1 W, AEC-Q200 Grade 0, 0603", Manufacturer=Vishay-Dale, Power_W=100mW, Supplier Part Number 1=541-3.40KHCT-ND, TempCo="100 ppm/C", Tolerance_%=1%, Value2=0.1W, Value_Code=3k40, ValueDisplayed=3.40k
R9: library part CMP-0022204-4, "RES, 20.0 k, 1%, 0.1 W, AEC-Q200 Grade 0, 0603", Manufacturer=Vishay-Dale, Power_W=100mW, Supplier Part Number 1=541-20.0KHCT-ND, TempCo="100 ppm/C", Tolerance_%=1%, Value2=0.1W, Value_Code=20k0, ValueDisplayed=20.0k
R10: library part CMP-0015024-3, "RES, 10.0, 1%, 1 W, AEC-Q200 Grade 0, 1218", Manufacturer=Vishay-Dale, Power_W=1W, Supplier Part Number 1=RCL10.0ACT-ND, TempCo="100 ppm/C", Tolerance_%=1%, Value_Code=10R0, ValueDisplayed=10.0
R11 R18: library part CMP-0022410-4, "RES, 40.2 k, 1%, 0.1 W, AEC-Q200 Grade 0, 0603", Manufacturer=Vishay-Dale, Power_W=100mW, Supplier Part Number 1=541-40.2KHCT-ND, TempCo="100 ppm/C", Tolerance_%=1%, Value2=0.1W, Value_Code=40k2, ValueDisplayed=40.2k
R12: library part CMP-0021990-4, "RES, 100 k, 1%, 0.1 W, AEC-Q200 Grade 0, 0603", Manufacturer=Vishay-Dale, Power_W=100mW, Supplier Part Number 1=541-100KHCT-ND, TempCo="100 ppm/C", Tolerance_%=1%, Value2=0.1W, Value_Code=100k
R13 R24 R40 R56 R57 R58 R59 R61 R64: library part CMP-0023343-3, "RES, 0, 1%, 0.1 W, AEC-Q200 Grade 0, 0603", Manufacturer="Stackpole Electronics Inc", Power_W=100mW, Supplier Part Number 1=RMCF0603ZT0R00CT-ND, TempCo=ppm/C, Tolerance_%=1%, Value2=0.1W, Value_Code=0
R14 R21: library part CMP-0022589-4, "RES, 75.0 k, 1%, 0.1 W, AEC-Q200 Grade 0, 0603", Manufacturer=Vishay-Dale, Power_W=100mW, Supplier Part Number 1=541-75.0KHCT-ND, TempCo="100 ppm/C", Tolerance_%=1%, Value2=0.1W, Value_Code=75k0, ValueDisplayed=75.0k
R15: library part CMP-0023073-5, "RES, 39.0 k, 1%, 0.1 W, 0603", Manufacturer=Yageo, Power_W=100mW, Supplier Part Number 1=311-39.0KHRCT-ND, TempCo="100 ppm/C", Tolerance_%=1%, Value2=0.1W, Value_Code=39k0, ValueDisplayed=39.0k
R16 R37 R53: library part CMP-0022237-4, "RES, 24.9 k, 1%, 0.1 W, AEC-Q200 Grade 0, 0603", Manufacturer=Vishay-Dale, Power_W=100mW, Supplier Part Number 1=541-24.9KHCT-ND, TempCo="100 ppm/C", Tolerance_%=1%, Value2=0.1W, Value_Code=24k9, ValueDisplayed=24.9k
R17: library part CMP-0022330-4, "RES, 31.6 k, 1%, 0.1 W, AEC-Q200 Grade 0, 0603", Manufacturer=Vishay-Dale, Power_W=100mW, Supplier Part Number 1=541-31.6KHCT-ND, TempCo="100 ppm/C", Tolerance_%=1%, Value2=0.1W, Value_Code=31k6, ValueDisplayed=31.6k
R19: library part CMP-0022443-4, "RES, 48.7 k, 1%, 0.1 W, AEC-Q200 Grade 0, 0603", Manufacturer=Vishay-Dale, Power_W=100mW, Supplier Part Number 1=541-48.7KHCT-ND, TempCo="100 ppm/C", Tolerance_%=1%, Value2=0.1W, Value_Code=48k7, ValueDisplayed=48.7k
R20: library part CMP-0022536-4, "RES, 61.9 k, 1%, 0.1 W, AEC-Q200 Grade 0, 0603", Manufacturer=Vishay-Dale, Power_W=100mW, Supplier Part Number 1=541-61.9KHCT-ND, TempCo="100 ppm/C", Tolerance_%=1%, Value2=0.1W, Value_Code=61k9, ValueDisplayed=61.9k
R22: library part CMP-0022651-4, "RES, 90.9 k, 1%, 0.1 W, AEC-Q200 Grade 0, 0603", Manufacturer=Vishay-Dale, Power_W=100mW, Supplier Part Number 1=541-90.9KHCT-ND, TempCo="100 ppm/C", Tolerance_%=1%, Value2=0.1W, Value_Code=90k9, ValueDisplayed=90.9k
R23: library part CMP-0022008-4, "RES, 110 k, 1%, 0.1 W, AEC-Q200 Grade 0, 0603", Manufacturer=Vishay-Dale, Power_W=100mW, Supplier Part Number 1=541-110KHCT-ND, TempCo="100 ppm/C", Tolerance_%=1%, Value2=0.1W, Value_Code=110k
R25 R41: library part CMP-0022481-5, "RES, 511, 1%, 0.1 W, AEC-Q200 Grade 0, 0603", Manufacturer=Vishay-Dale, Power_W=100mW, Supplier Part Number 1=541-511HCT-ND, TempCo="100 ppm/C", Tolerance_%=1%, Value2=0.1W, Value_Code=511R, ValueDisplayed=511
R26 R42: library part CMP-0022120-4, "RES, 1.30 k, 1%, 0.1 W, AEC-Q200 Grade 0, 0603", Manufacturer=Vishay-Dale, Power_W=100mW, Supplier Part Number 1=541-1.30KHCT-ND, TempCo="100 ppm/C", Tolerance_%=1%, Value2=0.1W, Value_Code=1k30, ValueDisplayed=1.30k
R27 R43: library part CMP-0022135-4, "RES, 1.87 k, 1%, 0.1 W, AEC-Q200 Grade 0, 0603", Manufacturer=Vishay-Dale, Power_W=100mW, Supplier Part Number 1=541-1.87KHCT-ND, TempCo="100 ppm/C", Tolerance_%=1%, Value2=0.1W, Value_Code=1k87, ValueDisplayed=1.87k
R28 R44: library part CMP-0022281-4, "RES, 2.74 k, 1%, 0.1 W, AEC-Q200 Grade 0, 0603", Manufacturer=Vishay-Dale, Power_W=100mW, Supplier Part Number 1=541-2.74KHCT-ND, TempCo="100 ppm/C", Tolerance_%=1%, Value2=0.1W, Value_Code=2k74, ValueDisplayed=2.74k
R29 R45: library part CMP-0022381-4, "RES, 3.83 k, 1%, 0.1 W, AEC-Q200 Grade 0, 0603", Manufacturer=Vishay-Dale, Power_W=100mW, Supplier Part Number 1=541-3.83KHCT-ND, TempCo="100 ppm/C", Tolerance_%=1%, Value2=0.1W, Value_Code=3k83, ValueDisplayed=3.83k
R30 R46: library part CMP-0022509-4, "RES, 5.11 k, 1%, 0.1 W, AEC-Q200 Grade 0, 0603", Manufacturer=Vishay-Dale, Power_W=100mW, Supplier Part Number 1=541-5.11KHCT-ND, TempCo="100 ppm/C", Tolerance_%=1%, Value2=0.1W, Value_Code=5k11, ValueDisplayed=5.11k
R31 R47: library part CMP-0022561-4, "RES, 6.49 k, 1%, 0.1 W, AEC-Q200 Grade 0, 0603", Manufacturer=Vishay-Dale, Power_W=100mW, Supplier Part Number 1=541-6.49KHCT-ND, TempCo="100 ppm/C", Tolerance_%=1%, Value2=0.1W, Value_Code=6k49, ValueDisplayed=6.49k
R32 R48: library part CMP-0022635-4, "RES, 8.25 k, 1%, 0.1 W, AEC-Q200 Grade 0, 0603", Manufacturer=Vishay-Dale, Power_W=100mW, Supplier Part Number 1=541-8.25KHCT-ND, TempCo="100 ppm/C", Tolerance_%=1%, Value2=0.1W, Value_Code=8k25, ValueDisplayed=8.25k
R33 R49: library part CMP-0022000-4, "RES, 10.5 k, 1%, 0.1 W, AEC-Q200 Grade 0, 0603", Manufacturer=Vishay-Dale, Power_W=100mW, Supplier Part Number 1=541-10.5KHCT-ND, TempCo="100 ppm/C", Tolerance_%=1%, Value2=0.1W, Value_Code=10k5, ValueDisplayed=10.5k
R34 R50: library part CMP-0022043-4, "RES, 13.3 k, 1%, 0.1 W, AEC-Q200 Grade 0, 0603", Manufacturer=Vishay-Dale, Power_W=100mW, Supplier Part Number 1=541-13.3KHCT-ND, TempCo="100 ppm/C", Tolerance_%=1%, Value2=0.1W, Value_Code=13k3, ValueDisplayed=13.3k
R35 R51: library part CMP-0022079-4, "RES, 16.2 k, 1%, 0.1 W, AEC-Q200 Grade 0, 0603", Manufacturer=Vishay-Dale, Power_W=100mW, Supplier Part Number 1=541-16.2KHCT-ND, TempCo="100 ppm/C", Tolerance_%=1%, Value2=0.1W, Value_Code=16k2, ValueDisplayed=16.2k
R36 R52: library part CMP-0022205-4, "RES, 20.5 k, 1%, 0.1 W, AEC-Q200 Grade 0, 0603", Manufacturer=Vishay-Dale, Power_W=100mW, Supplier Part Number 1=541-20.5KHCT-ND, TempCo="100 ppm/C", Tolerance_%=1%, Value2=0.1W, Value_Code=20k5, ValueDisplayed=20.5k
R38 R54: library part CMP-0022324-4, "RES, 30.1 k, 1%, 0.1 W, AEC-Q200 Grade 0, 0603", Manufacturer=Vishay-Dale, Power_W=100mW, Supplier Part Number 1=541-30.1KHCT-ND, TempCo="100 ppm/C", Tolerance_%=1%, Value2=0.1W, Value_Code=30k1, ValueDisplayed=30.1k
R39 R55: library part CMP-0022356-4, "RES, 36.5 k, 1%, 0.1 W, AEC-Q200 Grade 0, 0603", Manufacturer=Vishay-Dale, Power_W=100mW, Supplier Part Number 1=541-36.5KHCT-ND, TempCo="100 ppm/C", Tolerance_%=1%, Value2=0.1W, Value_Code=36k5, ValueDisplayed=36.5k
R60: library part CMP-0022490-4, "RES, 53.6 k, 1%, 0.1 W, AEC-Q200 Grade 0, 0603", Manufacturer=Vishay-Dale, Power_W=100mW, Supplier Part Number 1=541-53.6KHCT-ND, TempCo="100 ppm/C", Tolerance_%=1%, Value2=0.1W, Value_Code=53k6, ValueDisplayed=53.6k
R65: library part CMP-0022548-4, "RES, 66.5 k, 1%, 0.1 W, AEC-Q200 Grade 0, 0603", Manufacturer=Vishay-Dale, Power_W=100mW, Supplier Part Number 1=541-66.5KHCT-ND, TempCo="100 ppm/C", Tolerance_%=1%, Value2=0.1W, Value_Code=66k5, ValueDisplayed=66.5k
S1 S2 S3 S4 S5: library part CMP-0002229-1, "Switch, SPST, 8 Pos, 25mA, 24VDC, SMD", CurrentRating_mA=25A, Manufacturer="CTS Electrocomponents", Supplier Part Number 1=CT2188LPST-ND
SH-JP1 SH-JP2 SH-JP3 SH-JP4 SH-JP5 SH-JP6 SH-JP7: library part CMP-0003642-1, "Shunt, 100mil, Flash Gold, Black", Manufacturer="Sullins Connector Solutions", Supplier Part Number 1=S9001-ND
T1 T2 T3 T4: library part CMP-0075010-2, "Terminal 70A Lug", Manufacturer=Panduit, Supplier Part Number 1=CXS70-14-C-ND
TP1: library part CMP-0067620-1, "PC Test Point, SMT", Manufacturer="TE Connectivity", Supplier Part Number 1=A106145CT-ND
U1: library part CMP-0125772-1, "2.5MHz 42V wide-VIN synchronous GaN boost converter with output voltage tracking 22-VQFN-FCRLF -40 to 125", Manufacturer="Texas Instruments", Max Supply Voltage=42V, Min Supply Voltage=2.5V, Operating Temperature Range="-40°C to +125°C", Output Voltage=6-60V, Switching Frequency=300-2500kHz
ZZ1: library part CMP-0003616-3
ZZ2: library part CMP-0077236-1
ZZ3: library part CMP-0077237-1
ZZ4: library part CMP-0077238-1
ZZ5 ZZ6 ZZ7 ZZ8 ZZ9 ZZ10 ZZ11: library part CMP-0077238-1, "These assemblies must comply with workmanship standards IPC-A-610 Class 2, unless otherwise specified."

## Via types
v1: diameter 24, hole 8, Top Layer to Bottom Layer, tented both sides, 935 vias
